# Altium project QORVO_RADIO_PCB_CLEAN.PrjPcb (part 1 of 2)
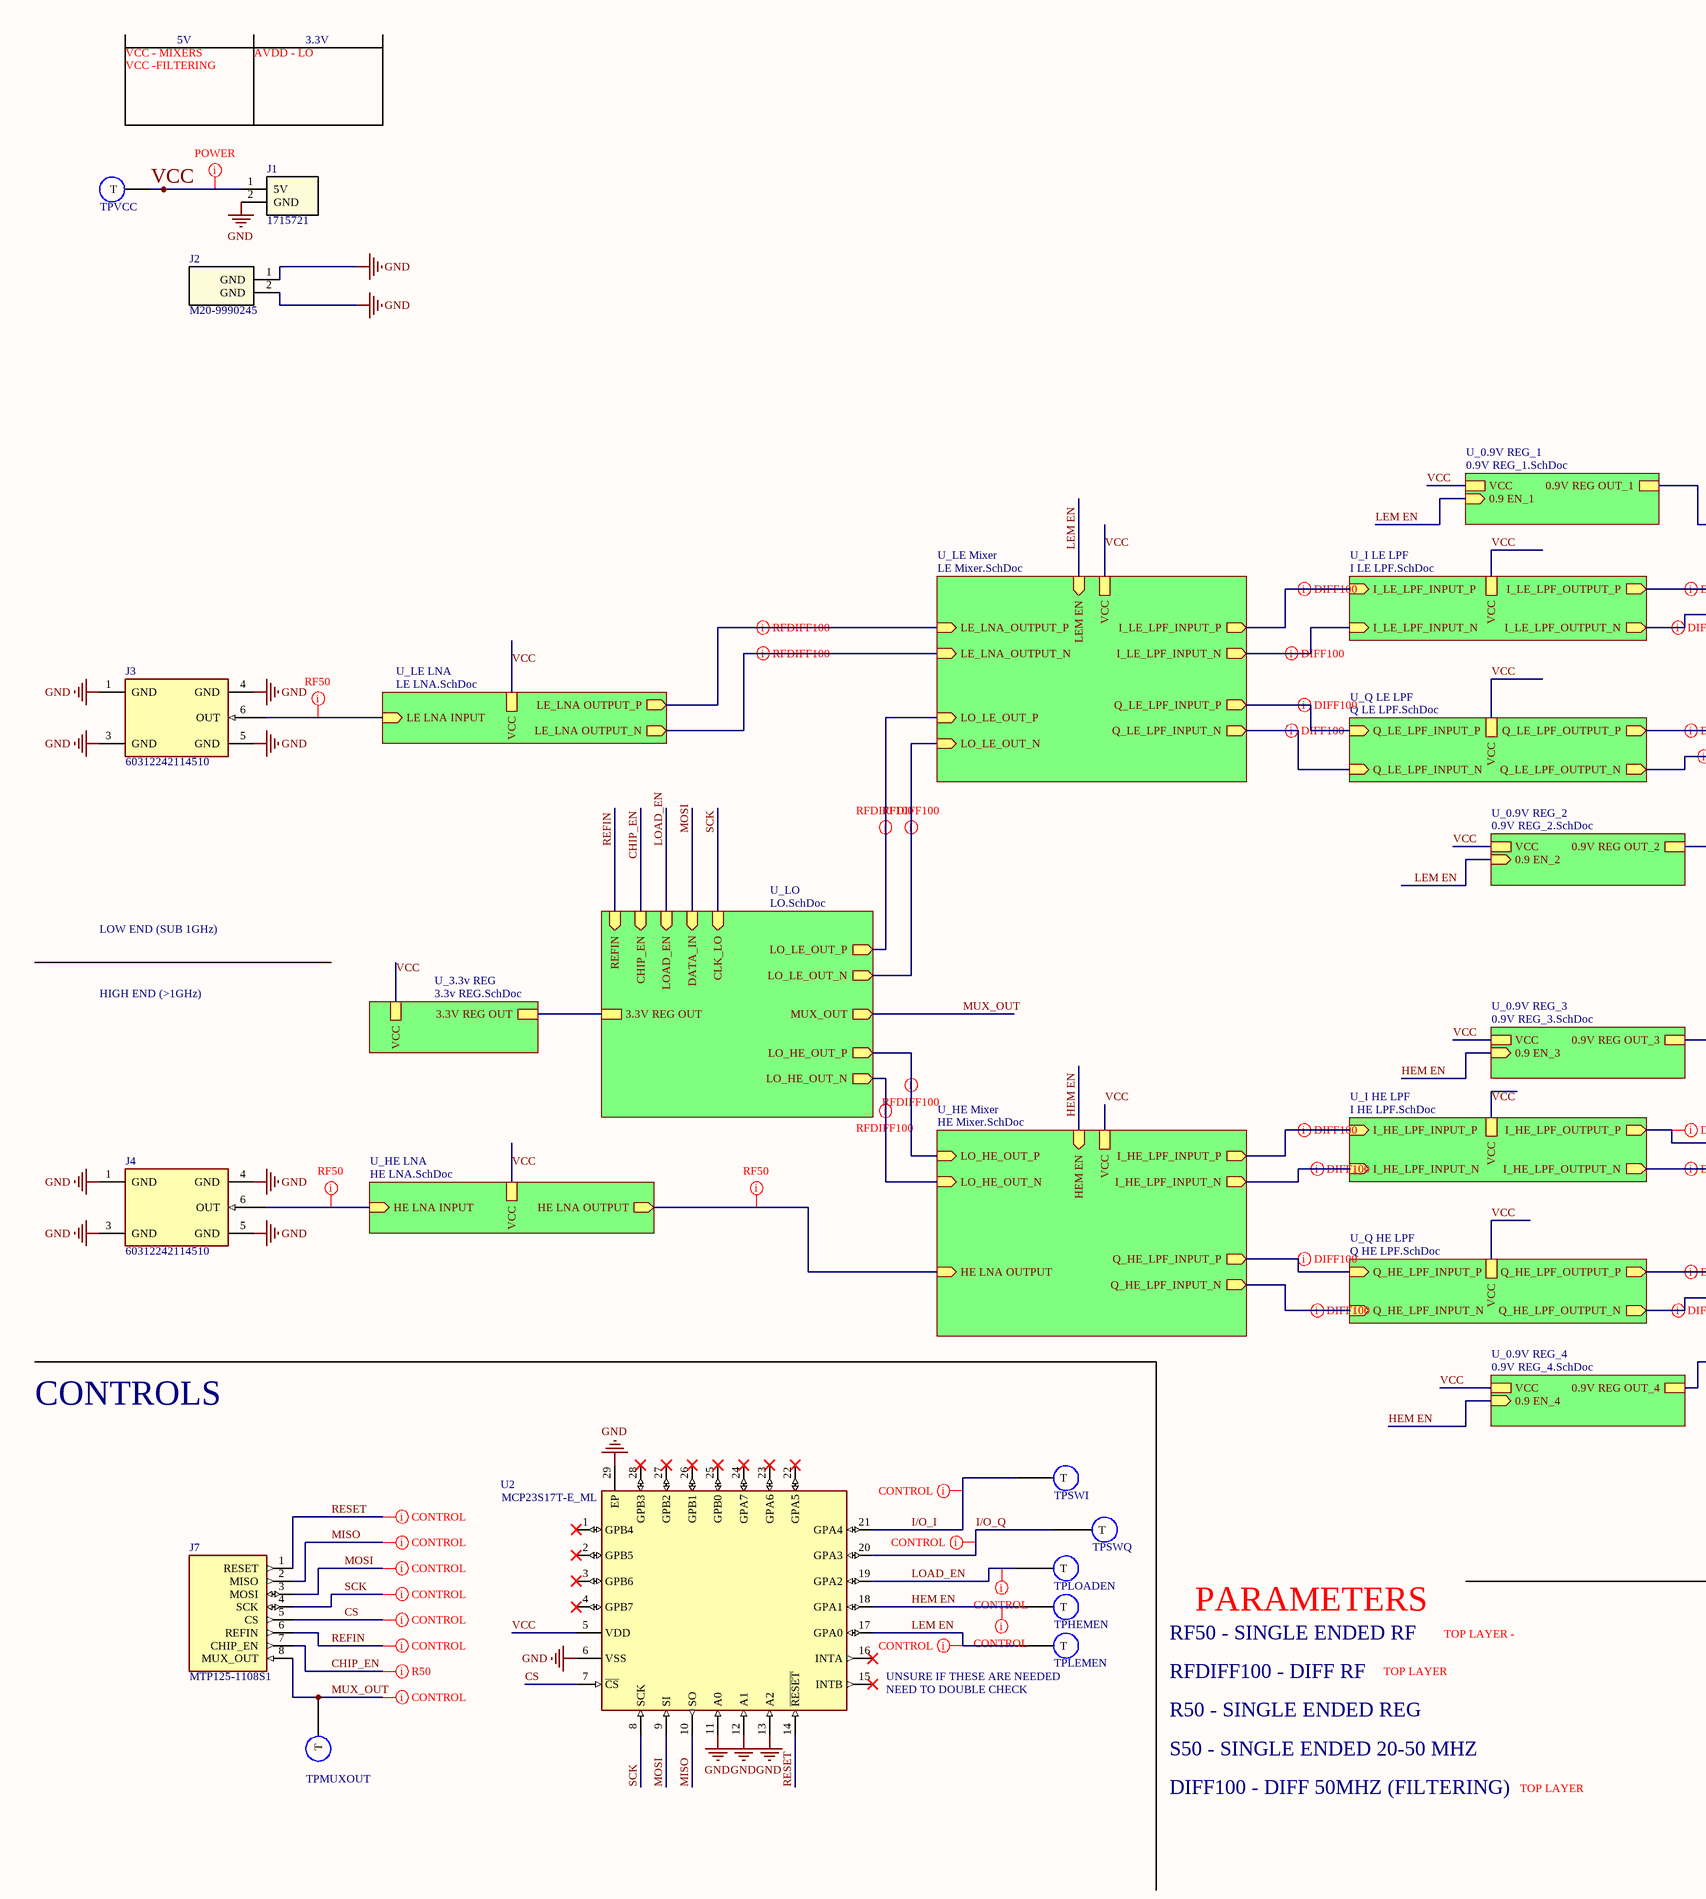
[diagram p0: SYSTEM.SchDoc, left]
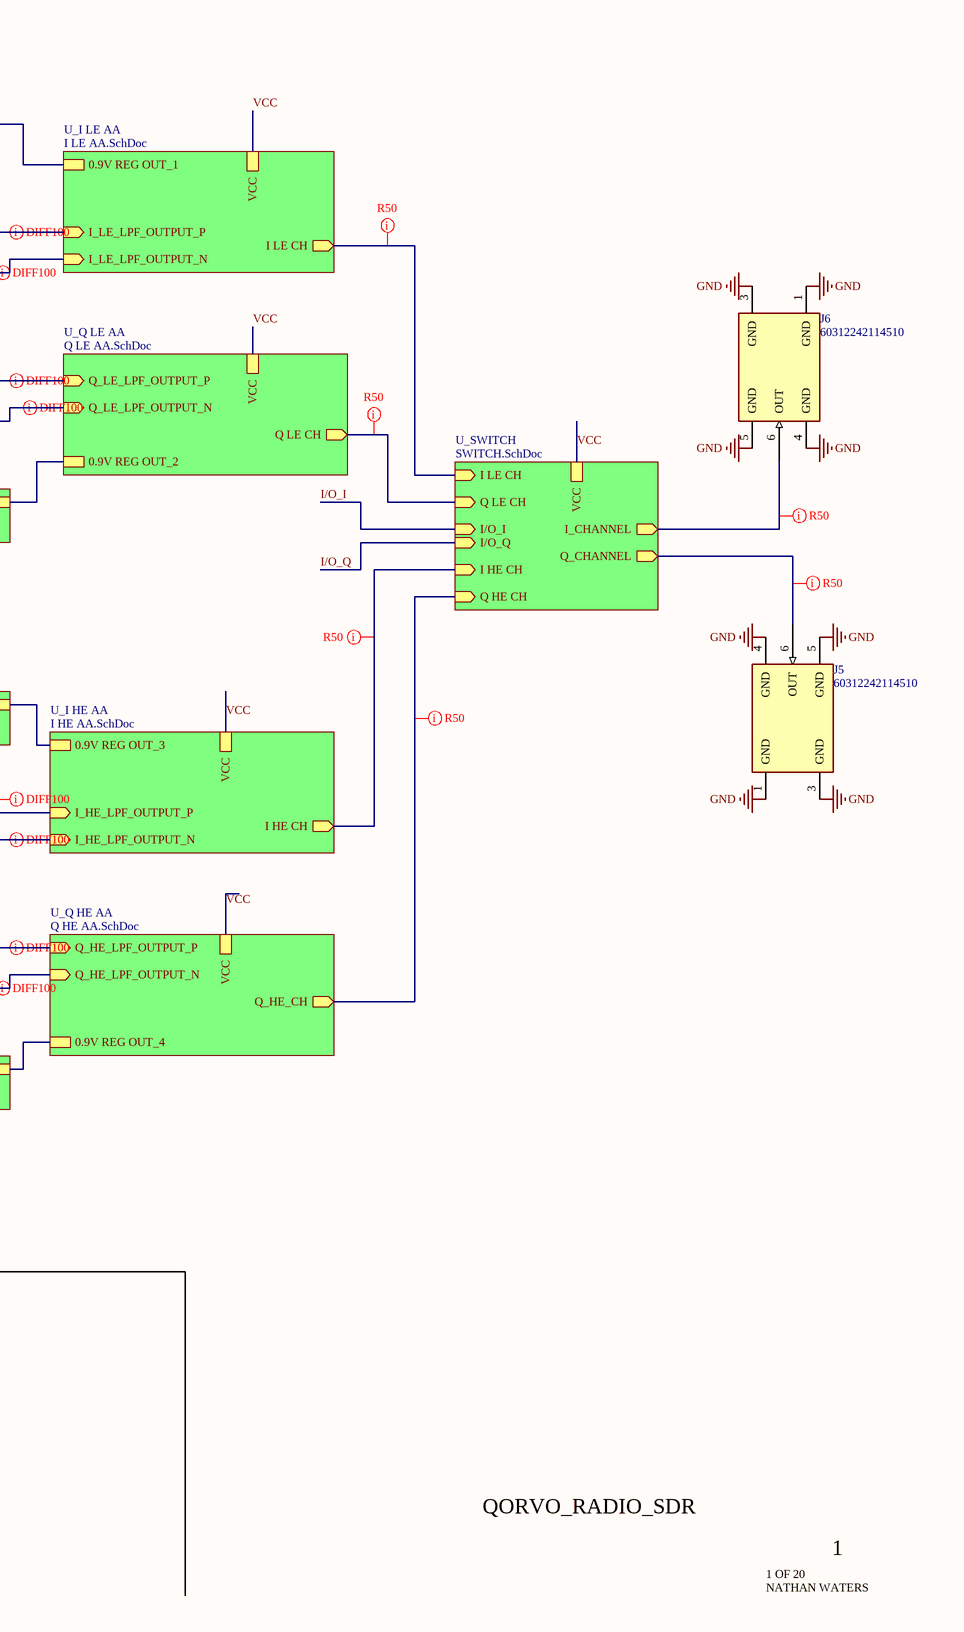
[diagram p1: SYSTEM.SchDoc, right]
20 sheets, 302 parts. Net scope: hierarchical (ports join the sheet entries above them; power ports are global).
Board file: QORVO_RADIO_PCB_FINAL.PcbDoc
Sheets:
  SYSTEM.SchDoc
    U_HE LNA = HE LNA.SchDoc
    U_3.3v REG = 3.3v REG.SchDoc
    U_SWITCH = SWITCH.SchDoc
    U_0.9V REG_1 = 0.9V REG_1.SchDoc
    U_0.9V REG_2 = 0.9V REG_2.SchDoc
    U_0.9V REG_3 = 0.9V REG_3.SchDoc
    U_0.9V REG_4 = 0.9V REG_4.SchDoc
    U_LE LNA = LE LNA.SchDoc
    U_LE Mixer = LE Mixer.SchDoc
    U_LO = LO.SchDoc
    U_HE Mixer = HE Mixer.SchDoc
    U_I LE LPF = I LE LPF.SchDoc
    U_Q LE LPF = Q LE LPF.SchDoc
    U_I HE LPF = I HE LPF.SchDoc
    U_Q HE LPF = Q HE LPF.SchDoc
    U_Q HE AA = Q HE AA.SchDoc
    U_I HE AA = I HE AA.SchDoc
    U_Q LE AA = Q LE AA.SchDoc
    U_I LE AA = I LE AA.SchDoc

## Sheet SYSTEM.SchDoc
size C; SheetNumber: 1; SheetTotal: 20

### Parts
J1  1715721  [1715721]
J2  M20-9990245  [GND_TEST]
J3  60312242114510  [60312242114510]
J4  60312242114510  [60312242114510]
J5  60312242114510  [60312242114510]
J6  60312242114510  [60312242114510]
J7  MTP125-1108S1  [M20-9990845]
TPHEMEN  TEST_POINT  [TEST POINT]  (value not drawn)  (no BOM)
TPLEMEN  TEST_POINT  [TEST POINT]  (value not drawn)  (no BOM)
TPLOADEN  TEST_POINT  [TEST POINT]  (value not drawn)  (no BOM)
TPMUXOUT  TEST_POINT  [TEST POINT]  (value not drawn)  (no BOM)
TPSWI  TEST_POINT  [TEST POINT]  (value not drawn)  (no BOM)
TPSWQ  TEST_POINT  [TEST POINT]  (value not drawn)  (no BOM)
TPVCC  TEST_POINT  [TEST POINT]  (value not drawn)  (no BOM)
U2  MCP23S17T-E_ML  [MCP23S17T-E_ML]

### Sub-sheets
U_0.9V REG_1 = 0.9V REG_1.SchDoc: VCC, 0.9V REG OUT_1, 0.9 EN_1 (in)
U_0.9V REG_2 = 0.9V REG_2.SchDoc: VCC, 0.9V REG OUT_2, 0.9 EN_2 (in)
U_0.9V REG_3 = 0.9V REG_3.SchDoc: VCC, 0.9V REG OUT_3, 0.9 EN_3 (in)
U_0.9V REG_4 = 0.9V REG_4.SchDoc: VCC, 0.9V REG OUT_4, 0.9 EN_4 (in)
U_3.3v REG = 3.3v REG.SchDoc: 3.3V REG OUT, VCC
U_HE LNA = HE LNA.SchDoc: HE LNA INPUT (in), HE LNA OUTPUT (out), VCC
U_HE Mixer = HE Mixer.SchDoc: HE LNA OUTPUT (in), HEM EN (in), VCC, LO_HE_OUT_N (in), LO_HE_OUT_P (in), Q_HE_LPF_INPUT_P (out), Q_HE_LPF_INPUT_N (out), I_HE_LPF_INPUT_N (out), I_HE_LPF_INPUT_P (out)
U_I HE AA = I HE AA.SchDoc: I_HE_LPF_OUTPUT_P (in), I_HE_LPF_OUTPUT_N (in), VCC, 0.9V REG OUT_3, I HE CH (out)
U_I HE LPF = I HE LPF.SchDoc: I_HE_LPF_INPUT_P (in), I_HE_LPF_INPUT_N (in), VCC, I_HE_LPF_OUTPUT_P (out), I_HE_LPF_OUTPUT_N (out)
U_I LE AA = I LE AA.SchDoc: I_LE_LPF_OUTPUT_P (in), I_LE_LPF_OUTPUT_N (in), VCC, 0.9V REG OUT_1, I LE CH (out)
U_I LE LPF = I LE LPF.SchDoc: I_LE_LPF_INPUT_P (in), I_LE_LPF_INPUT_N (in), VCC, I_LE_LPF_OUTPUT_P (out), I_LE_LPF_OUTPUT_N (out)
U_LE LNA = LE LNA.SchDoc: LE LNA INPUT (in), VCC, LE_LNA OUTPUT_P (out), LE_LNA OUTPUT_N (out)
U_LE Mixer = LE Mixer.SchDoc: LE_LNA_OUTPUT_P (in), LE_LNA_OUTPUT_N (in), LEM EN (in), VCC, LO_LE_OUT_N (in), Q_LE_LPF_INPUT_P (out), Q_LE_LPF_INPUT_N (out), I_LE_LPF_INPUT_N (out), I_LE_LPF_INPUT_P (out), LO_LE_OUT_P (in)
U_LO = LO.SchDoc: CLK_LO (in), DATA_IN (in), LOAD_EN (in), CHIP_EN (in), LO_LE_OUT_N (out), REFIN (in), MUX_OUT (out), LO_HE_OUT_P (out), LO_HE_OUT_N (out), 3.3V REG OUT, LO_LE_OUT_P (out)
U_Q HE AA = Q HE AA.SchDoc: Q_HE_LPF_OUTPUT_P (in), Q_HE_LPF_OUTPUT_N (in), VCC, 0.9V REG OUT_4, Q_HE_CH (out)
U_Q HE LPF = Q HE LPF.SchDoc: Q_HE_LPF_INPUT_P (in), Q_HE_LPF_INPUT_N (in), VCC, Q_HE_LPF_OUTPUT_P (out), Q_HE_LPF_OUTPUT_N (out)
U_Q LE AA = Q LE AA.SchDoc: Q_LE_LPF_OUTPUT_P (in), Q_LE_LPF_OUTPUT_N (in), VCC, 0.9V REG OUT_2, Q LE CH (out)
U_Q LE LPF = Q LE LPF.SchDoc: Q_LE_LPF_INPUT_P (in), Q_LE_LPF_INPUT_N (in), VCC, Q_LE_LPF_OUTPUT_P (out), Q_LE_LPF_OUTPUT_N (out)
U_SWITCH = SWITCH.SchDoc: I/O_I (in), I HE CH (in), Q HE CH (in), I/O_Q (in), VCC, I_CHANNEL (out), I LE CH (in), Q LE CH (in), Q_CHANNEL (out)

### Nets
GND: J1.2(GND) J2.1(GND) J2.2(GND) J3.1(GND) J3.3(GND) J3.4(GND) J3.5(GND) J4.1(GND) J4.3(GND) J4.4(GND) J4.5(GND) J5.1(GND) J5.3(GND) J5.4(GND) J5.5(GND) J6.1(GND) J6.3(GND) J6.4(GND) J6.5(GND) U2.6(VSS) U2.11(A0) U2.12(A1) U2.13(A2) U2.29(EP)
0.9V REG OUT_1: sheet U_0.9V REG_1/0.9V REG OUT_1, sheet U_I LE AA/0.9V REG OUT_1
0.9V REG OUT_2: sheet U_0.9V REG_2/0.9V REG OUT_2, sheet U_Q LE AA/0.9V REG OUT_2
0.9V REG OUT_3: sheet U_0.9V REG_3/0.9V REG OUT_3, sheet U_I HE AA/0.9V REG OUT_3
0.9V REG OUT_4: sheet U_0.9V REG_4/0.9V REG OUT_4, sheet U_Q HE AA/0.9V REG OUT_4
AVDD: sheet U_3.3v REG/3.3V REG OUT, sheet U_LO/3.3V REG OUT
CHIP_EN: J7.7(CHIP_EN) ; sheet U_LO/CHIP_EN
CS: J7.5(CS) U2.7(~{CS})
HE LNA OUTPUT: sheet U_HE LNA/HE LNA OUTPUT, sheet U_HE Mixer/HE LNA OUTPUT
HEM EN: TPHEMEN.1(T) U2.18(GPA1) ; sheet U_0.9V REG_3/0.9 EN_3, sheet U_0.9V REG_4/0.9 EN_4, sheet U_HE Mixer/HEM EN
I HE CH: sheet U_SWITCH/I HE CH, sheet U_I HE AA/I HE CH
I LE CH: sheet U_SWITCH/I LE CH, sheet U_I LE AA/I LE CH
I/O_I: TPSWI.1(T) U2.21(GPA4) ; sheet U_SWITCH/I/O_I
I/O_Q: TPSWQ.1(T) U2.20(GPA3) ; sheet U_SWITCH/I/O_Q
I_HE_LPF_INPUT_N: sheet U_HE Mixer/I_HE_LPF_INPUT_N, sheet U_I HE LPF/I_HE_LPF_INPUT_N
I_HE_LPF_INPUT_P: sheet U_HE Mixer/I_HE_LPF_INPUT_P, sheet U_I HE LPF/I_HE_LPF_INPUT_P
I_HE_LPF_OUTPUT_N: sheet U_I HE LPF/I_HE_LPF_OUTPUT_N, sheet U_I HE AA/I_HE_LPF_OUTPUT_N
I_HE_LPF_OUTPUT_P: sheet U_I HE LPF/I_HE_LPF_OUTPUT_P, sheet U_I HE AA/I_HE_LPF_OUTPUT_P
I_LE_LPF_INPUT_N: sheet U_LE Mixer/I_LE_LPF_INPUT_N, sheet U_I LE LPF/I_LE_LPF_INPUT_N
I_LE_LPF_INPUT_P: sheet U_LE Mixer/I_LE_LPF_INPUT_P, sheet U_I LE LPF/I_LE_LPF_INPUT_P
I_LE_LPF_OUTPUT_N: sheet U_I LE LPF/I_LE_LPF_OUTPUT_N, sheet U_I LE AA/I_LE_LPF_OUTPUT_N
I_LE_LPF_OUTPUT_P: sheet U_I LE LPF/I_LE_LPF_OUTPUT_P, sheet U_I LE AA/I_LE_LPF_OUTPUT_P
LE_LNA OUTPUT_N: sheet U_LE LNA/LE_LNA OUTPUT_N, sheet U_LE Mixer/LE_LNA_OUTPUT_N
LE_LNA OUTPUT_P: sheet U_LE LNA/LE_LNA OUTPUT_P, sheet U_LE Mixer/LE_LNA_OUTPUT_P
LEM EN: TPLEMEN.1(T) U2.17(GPA0) ; sheet U_0.9V REG_1/0.9 EN_1, sheet U_0.9V REG_2/0.9 EN_2, sheet U_LE Mixer/LEM EN
LO_HE_OUT_N: sheet U_LO/LO_HE_OUT_N, sheet U_HE Mixer/LO_HE_OUT_N
LO_HE_OUT_P: sheet U_LO/LO_HE_OUT_P, sheet U_HE Mixer/LO_HE_OUT_P
LO_LE_OUT_N: sheet U_LE Mixer/LO_LE_OUT_N, sheet U_LO/LO_LE_OUT_N
LO_LE_OUT_P: sheet U_LE Mixer/LO_LE_OUT_P, sheet U_LO/LO_LE_OUT_P
LOAD_EN: TPLOADEN.1(T) U2.19(GPA2) ; sheet U_LO/LOAD_EN
MISO: J7.2(MISO) U2.10(SO)
MOSI: J7.3(MOSI) U2.9(SI) ; sheet U_LO/DATA_IN
MUX_OUT: J7.8(MUX_OUT) TPMUXOUT.1(T) ; sheet U_LO/MUX_OUT
Q HE CH: sheet U_SWITCH/Q HE CH, sheet U_Q HE AA/Q_HE_CH
Q LE CH: sheet U_SWITCH/Q LE CH, sheet U_Q LE AA/Q LE CH
Q_HE_LPF_INPUT_N: sheet U_HE Mixer/Q_HE_LPF_INPUT_N, sheet U_Q HE LPF/Q_HE_LPF_INPUT_N
Q_HE_LPF_INPUT_P: sheet U_HE Mixer/Q_HE_LPF_INPUT_P, sheet U_Q HE LPF/Q_HE_LPF_INPUT_P
Q_HE_LPF_OUTPUT_N: sheet U_Q HE LPF/Q_HE_LPF_OUTPUT_N, sheet U_Q HE AA/Q_HE_LPF_OUTPUT_N
Q_HE_LPF_OUTPUT_P: sheet U_Q HE LPF/Q_HE_LPF_OUTPUT_P, sheet U_Q HE AA/Q_HE_LPF_OUTPUT_P
Q_LE_LPF_INPUT_N: sheet U_LE Mixer/Q_LE_LPF_INPUT_N, sheet U_Q LE LPF/Q_LE_LPF_INPUT_N
Q_LE_LPF_INPUT_P: sheet U_LE Mixer/Q_LE_LPF_INPUT_P, sheet U_Q LE LPF/Q_LE_LPF_INPUT_P
Q_LE_LPF_OUTPUT_N: sheet U_Q LE LPF/Q_LE_LPF_OUTPUT_N, sheet U_Q LE AA/Q_LE_LPF_OUTPUT_N
Q_LE_LPF_OUTPUT_P: sheet U_Q LE LPF/Q_LE_LPF_OUTPUT_P, sheet U_Q LE AA/Q_LE_LPF_OUTPUT_P
REFIN: J7.6(REFIN) ; sheet U_LO/REFIN
RESET: J7.1(RESET) U2.14(~{RESET})
SCK: J7.4(SCK) U2.8(SCK) ; sheet U_LO/CLK_LO
VCC: J1.1(5V) TPVCC.1(T) U2.5(VDD) ; sheet U_HE LNA/VCC, sheet U_3.3v REG/VCC, sheet U_SWITCH/VCC, sheet U_0.9V REG_1/VCC, sheet U_0.9V REG_2/VCC, sheet U_0.9V REG_3/VCC, sheet U_0.9V REG_4/VCC, sheet U_LE LNA/VCC, sheet U_LE Mixer/VCC, sheet U_HE Mixer/VCC, sheet U_I LE LPF/VCC, sheet U_Q LE LPF/VCC, sheet U_I HE LPF/VCC, sheet U_Q HE LPF/VCC, sheet U_Q HE AA/VCC, sheet U_I HE AA/VCC, sheet U_Q LE AA/VCC, sheet U_I LE AA/VCC
NetC53_1: J3.6(OUT) ; sheet U_LE LNA/LE LNA INPUT
NetC71_1: J4.6(OUT) ; sheet U_HE LNA/HE LNA INPUT
NetJ5_6: J5.6(OUT) ; sheet U_SWITCH/Q_CHANNEL
NetJ6_6: J6.6(OUT) ; sheet U_SWITCH/I_CHANNEL

Not connected (* = marked no-connect by the designer): U2 1(GPB4)* 2(GPB5)* 3(GPB6)* 4(GPB7)* 15(INTB)* 16(INTA)* 22(GPA5)* 23(GPA6)* 24(GPA7)* 25(GPB0)* 26(GPB1)* 27(GPB2)* 28(GPB3)*

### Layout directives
net class RF50: HE LNA OUTPUT, NetC53_1, NetC71_1
differential pair; differential pair class RFDIFF100: LE_LNA OUTPUT_N, LE_LNA OUTPUT_P, LO_HE_OUT_N, LO_HE_OUT_P, LO_LE_OUT_N, LO_LE_OUT_P
differential pair; differential pair class DIFF100: I_HE_LPF_INPUT_N, I_HE_LPF_INPUT_P, I_HE_LPF_OUTPUT_N, I_HE_LPF_OUTPUT_P, I_LE_LPF_INPUT_N, I_LE_LPF_INPUT_P, I_LE_LPF_OUTPUT_N, I_LE_LPF_OUTPUT_P, Q_HE_LPF_INPUT_N, Q_HE_LPF_INPUT_P, Q_HE_LPF_OUTPUT_N, Q_HE_LPF_OUTPUT_P, Q_LE_LPF_INPUT_N, Q_LE_LPF_INPUT_P, Q_LE_LPF_OUTPUT_N, Q_LE_LPF_OUTPUT_P
net class R50: CHIP_EN, I HE CH, I LE CH, NetJ5_6, NetJ6_6, Q HE CH, Q LE CH
net class CONTROLS: CS, HEM EN, I/O_I, I/O_Q, LEM EN, LOAD_EN, MISO, MOSI, MUX_OUT, REFIN, RESET, SCK
net class POWER: VCC

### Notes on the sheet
- VCC - MIXERS
- VCC -FILTERING
- 5V
- AVDD - LO
- 3.3V
- LOW END (SUB 1GHz)
- HIGH END (>1GHz)
- CONTROLS
- PARAMETERS
- UNSURE IF THESE ARE NEEDED
- (near U2) NEED TO DOUBLE CHECK
- RF50 - SINGLE ENDED RF
- RFDIFF100 - DIFF RF
- TOP LAYER
- TOP LAYER -
- R50 - SINGLE ENDED REG
- S50 - SINGLE ENDED 20-50 MHZ
- DIFF100 - DIFF 50MHZ (FILTERING)
- QORVO_RADIO_SDR
- NATHAN WATERS
- 1 OF 20
- 1

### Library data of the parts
J1 = 1715721: 1x2P 17.5A 250V Green 14~30 Direct Insert 5.08mm 1 2 Plugin,P=5.08mm Screw Terminal Blocks ROHS; Mfr_Name: Phoenix Contact
J2 = GND_TEST: 3A Direct Insert Policy 2.54mm 2P 6.1mm -40℃~+105℃ 3mm 2.54mm Single Row Brass Black Plugin,P=2.54mm  Pin Headers ROHS; Mfr_Name: Harwin
J3-J6 = 60312242114510: 1 SMA Board Edge 18GHz 50Ω -  RF Connectors / Coaxial Connectors ROHS
J7 = MTP125-1108S1: Direct Insert Policy 2.5mm 8P 6mm -40℃~+105℃ 3mm 2.54mm Single Row Black Brass 1x8P Plugin,P=2.54mm Pin Headers ROHS; MP: M20-9990645
TPHEMEN TPLEMEN TPLOADEN TPMUXOUT TPSWI TPSWQ TPVCC = TEST_POINT: TEST POINT
U2 = MCP23S17T-E_ML: 10MHz SPI QFN-28-EP(6x6) I/O Expanders ROHS; Manufacturer_Name: Microchip; Manufacturer_Part_Number: MCP23S17T-E/ML

## Sheet HE LNA.SchDoc
size A; SheetNumber: 8; SheetTotal: 20
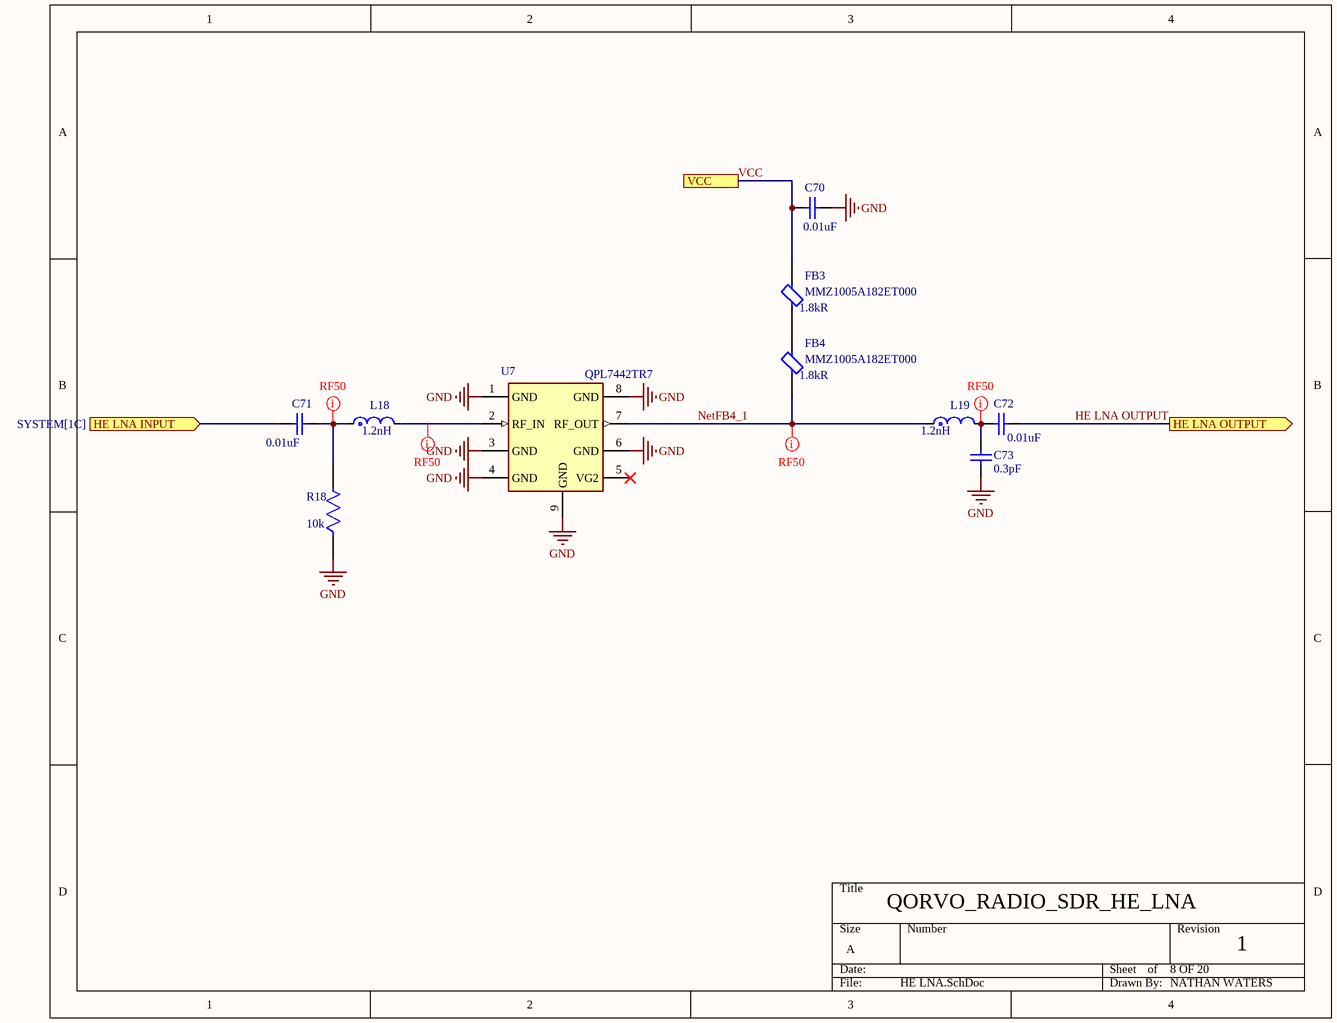
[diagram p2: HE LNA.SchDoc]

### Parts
C70  CAPACITANCE: 0.01uF  [0402 CAP_IND_RES]  (hidden comment: GRM155R71C103KA01D)
C71  CAPACITANCE: 0.01uF  [0402 CAP_IND_RES]  (hidden comment: GRM155R71C103KA01D)
C72  CAPACITANCE: 0.01uF  [0402 CAP_IND_RES]  (hidden comment: GRM155R71C103KA01D)
C73  CAPACITANCE: 0.3pF  [0402 CAP_IND_RES]  (hidden comment: GJM1555C1HR30WB01D)
FB3  MMZ1005A182ET000  Impeadance: 1.8kR  [0402 CAP_IND_RES]
FB4  MMZ1005A182ET000  Impeadance: 1.8kR  [0402 CAP_IND_RES]
L18  Inductance: 1.2nH  [0402 CAP_IND_RES]  (hidden comment: LQG15HS1N2S02D)
L19  Inductance: 1.2nH  [0402 CAP_IND_RES]  (hidden comment: LQG15HS1N2S02D)
R18  Resistance: 10k  [0402 CAP_IND_RES]  (hidden comment: CRCW040210K0FKEDC)
U7  QPL7442TR7  [QPL7442TR7]

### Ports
HE LNA INPUT (in, see SYSTEM[1C]), HE LNA OUTPUT (out, see SYSTEM[2C], HE Mixer[1C]), VCC (see SYSTEM[2C], 0.9V REG_1[3B], 0.9V REG_2[3B], 0.9V REG_3[3B], 0.9V REG_4[3B], 3.3v REG[3B], HE Mixer[3C], I HE AA[1B], I HE LPF[1A], I LE AA[1B], I LE LPF[1A], LE LNA[2A], LE Mixer[3C], Q HE AA[1B], Q HE LPF[1A], Q LE AA[1B], Q LE LPF[1B], SWITCH[4B])

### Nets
GND: C70.2 C73.1 R18.1 U7.1(GND) U7.3(GND) U7.4(GND) U7.6(GND) U7.8(GND) U7.9(GND)
HE LNA OUTPUT: C72.2 ; port HE LNA OUTPUT
NetFB4_1: FB4.1 L19.1 U7.7(RF_OUT)
VCC: C70.1 FB3.2 ; port VCC
NetC71_1: C71.1 ; port HE LNA INPUT
NetC71_2: C71.2 L18.1 R18.2
NetC72_1: C72.1 C73.2 L19.2
NetFB3_1: FB3.1 FB4.2
NetL18_2: L18.2 U7.2(RF_IN)

Not connected (* = marked no-connect by the designer): U7 5(VG2)*

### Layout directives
net class RF50: NetC71_2, NetC72_1, NetFB4_1, NetL18_2

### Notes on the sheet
- QORVO_RADIO_SDR_HE_LNA
- 8 OF 20
- 1
- NATHAN WATERS

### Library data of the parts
C70-C72 = 0402_CAP: Chip Capacitor, 10 nF, 16 V, 10%, -55 to 125 degC, 0402 (1005 Metric), RoHS, Tape and Reel
C73 = 0402_CAP: Multi-Layer Ceramic Capacitor 0.3pF C0G  ±0.05pF 0402 Paper T/R
FB3 FB4 = 0402_FERRITE_BEADS: Signal Line Ferrite Bead 1800Ω @ 100MHz 200mA DCR 2100mΩ SMD 0402
L18 L19 = 0402_IND: 1A 1.2nH 70mΩ 0402 Inductors (SMD) ROHS
R18 = 0402_RES: RES 10K OHM 1% 1/16W 0402
U7 = QPL7442TR7: Qorvo QPL7442TR7

## Sheet 3.3v REG.SchDoc
size A; SheetNumber: 3; SheetTotal: 20
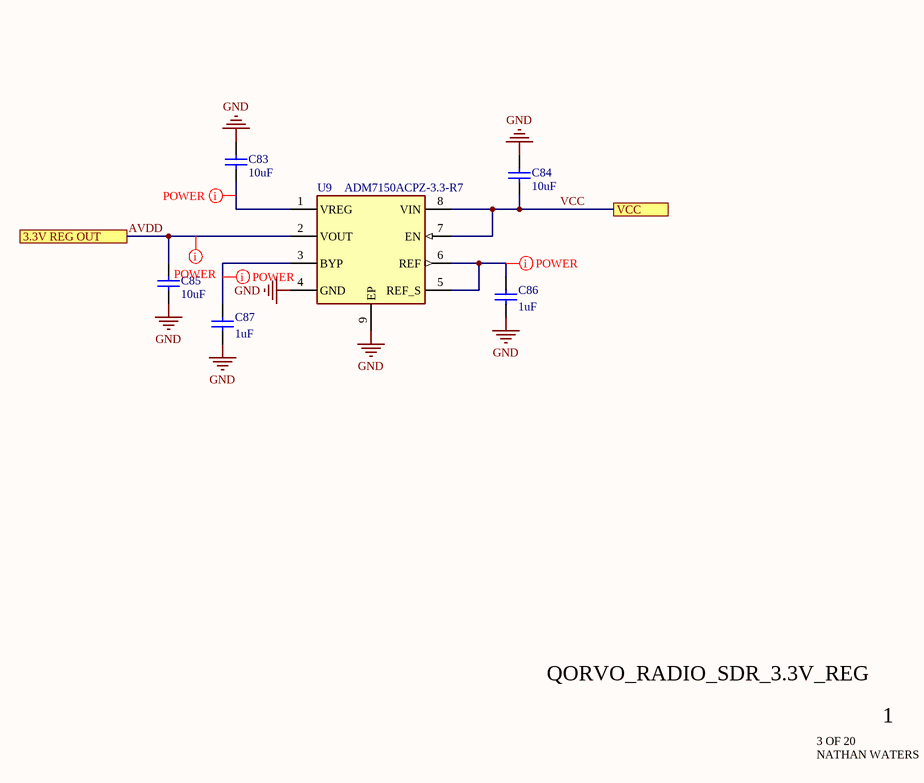
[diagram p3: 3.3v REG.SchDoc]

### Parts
C83  CAPACITANCE: 10uF  [0603_CAP]  (hidden comment: GRM188C81C106MA73D)
C84  CAPACITANCE: 10uF  [0603_CAP]  (hidden comment: GRM188C81C106MA73D)
C85  CAPACITANCE: 10uF  [0603_CAP]  (hidden comment: GRM188C81C106MA73D)
C86  CAPACITANCE: 1uF  [0402 CAP_IND_RES]  (hidden comment: GRM155R61H105KE05D)
C87  CAPACITANCE: 1uF  [0402 CAP_IND_RES]  (hidden comment: GRM155R61H105KE05D)
U9  ADM7150ACPZ-3.3-R7  [ADM7150ACPZ-3.3-R7]

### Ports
3.3V REG OUT (see SYSTEM[2C], LO[1A]), VCC (see SYSTEM[1C], 0.9V REG_1[3B], 0.9V REG_2[3B], 0.9V REG_3[3B], 0.9V REG_4[3B], HE LNA[2A], HE Mixer[3C], I HE AA[1B], I HE LPF[1A], I LE AA[1B], I LE LPF[1A], LE LNA[2A], LE Mixer[3C], Q HE AA[1B], Q HE LPF[1A], Q LE AA[1B], Q LE LPF[1B], SWITCH[4B])

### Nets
GND: C83.2 C84.2 C85.1 C86.1 C87.1 U9.4(GND) U9.9(EP)
AVDD: C85.2 U9.2(VOUT) ; port 3.3V REG OUT
VCC: C84.1 U9.7(EN) U9.8(VIN) ; port VCC
NetC83_1: C83.1 U9.1(VREG)
NetC86_2: C86.2 U9.5(REF_S) U9.6(REF)
NetC87_2: C87.2 U9.3(BYP)

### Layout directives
net class POWER: AVDD, NetC83_1, NetC86_2, NetC87_2

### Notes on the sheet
- QORVO_RADIO_SDR_3.3V_REG
- 3 OF 20
- 1
- NATHAN WATERS

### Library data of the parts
C83-C85 = 0603_CAP: Chip Multilayer Ceramic Capacitors for General Purpose, 0603, 10uF, X6S, 22%, 20%, 16V
C86 C87 = 0402_CAP: 50V 1uF X5R ±10% 0402  Multilayer Ceramic Capacitors MLCC - SMD/SMT ROHS
U9 = ADM7150ACPZ-3.3-R7: 800mA 68dB@(1MHz) Fixed 3.3V Positive electrode 16V LFCSP-8-EP(3x3) Voltage Regulators - Linear, Low Drop Out (LDO) Regulators ROHS; Manufacturer_Name: Analog Devices

## Sheet SWITCH.SchDoc
size A; SheetNumber: 2; SheetTotal: 20
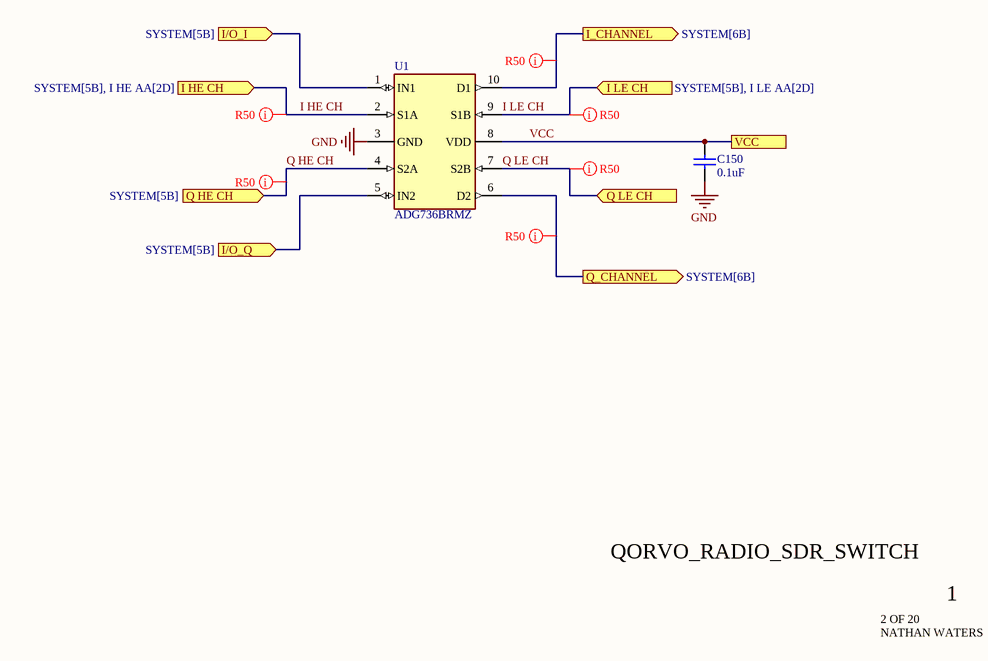
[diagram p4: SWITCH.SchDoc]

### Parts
C150  CAPACITANCE: 0.1uF  [0402 CAP_IND_RES]  (hidden comment: CL05B104KO5NNNC)
U1  ADG736BRMZ  [ADG736BRMZ]

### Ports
I HE CH (in, see SYSTEM[5B], I HE AA[2D]), I LE CH (in, see SYSTEM[5B], I LE AA[2D]), I/O_I (in, see SYSTEM[5B]), I/O_Q (in, see SYSTEM[5B]), I_CHANNEL (out, see SYSTEM[6B]), Q HE CH (in, see SYSTEM[5B]), Q LE CH (in, see SYSTEM[5B], Q LE AA[2D]), Q_CHANNEL (out, see SYSTEM[6B]), VCC (see SYSTEM[6B], 0.9V REG_1[3B], 0.9V REG_2[3B], 0.9V REG_3[3B], 0.9V REG_4[3B], 3.3v REG[3B], HE LNA[2A], HE Mixer[3C], I HE AA[1B], I HE LPF[1A], I LE AA[1B], I LE LPF[1A], LE LNA[2A], LE Mixer[3C], Q HE AA[1B], Q HE LPF[1A], Q LE AA[1B], Q LE LPF[1B])

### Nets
GND: C150.1 U1.3(GND)
I HE CH: U1.2(S1A) ; port I HE CH
I LE CH: U1.9(S1B) ; port I LE CH
I/O_I: U1.1(IN1) ; port I/O_I
I/O_Q: U1.5(IN2) ; port I/O_Q
Q HE CH: U1.4(S2A) ; port Q HE CH
Q LE CH: U1.7(S2B) ; port Q LE CH
VCC: C150.2 U1.8(VDD) ; port VCC
NetJ5_6: U1.6(D2) ; port Q_CHANNEL
NetJ6_6: U1.10(D1) ; port I_CHANNEL

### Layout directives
net class R50: I HE CH, I LE CH, NetJ5_6, NetJ6_6, Q HE CH, Q LE CH

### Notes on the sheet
- QORVO_RADIO_SDR_SWITCH
- 2 OF 20
- 1
- NATHAN WATERS

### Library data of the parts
C150 = 0402_CAP: 16V 100nF X7R ±10% 0402 Multilayer Ceramic Capacitors MLCC - SMD/SMT ROHS
U1 = ADG736BRMZ: 2 4Ω SPDT(SPDT) MSOP-10  Analog Switches, Multiplexers ROHS; Manufacturer_Name: Analog Devices

## Sheet 0.9V REG_1.SchDoc
size A; SheetNumber: 17; SheetTotal: 20
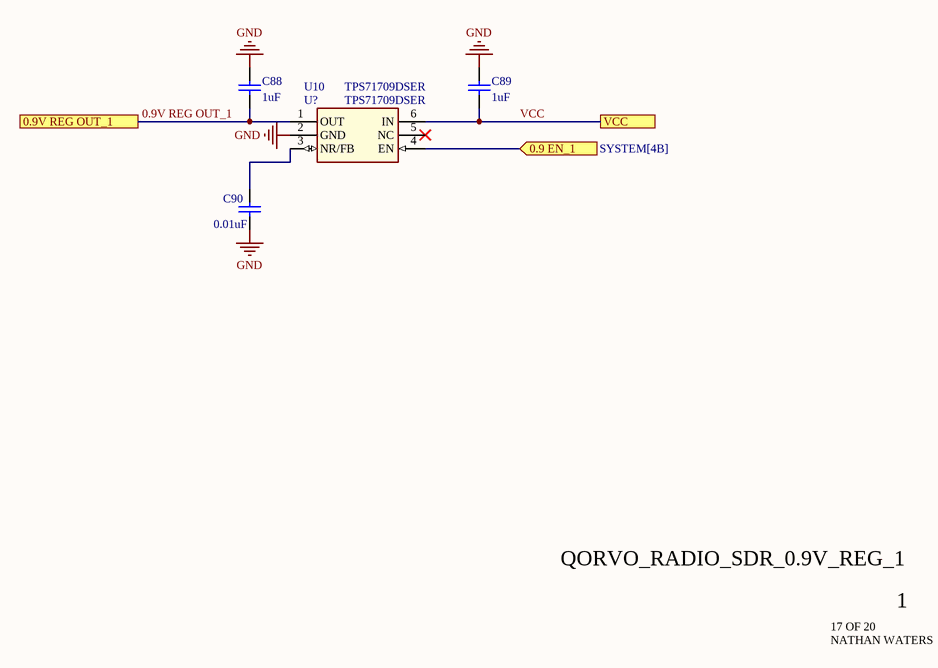
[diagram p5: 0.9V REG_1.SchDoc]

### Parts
C88  CAPACITANCE: 1uF  [0402 CAP_IND_RES]  (hidden comment: GRM155R61H105KE05D)
C89  CAPACITANCE: 1uF  [0402 CAP_IND_RES]  (hidden comment: GRM155R61H105KE05D)
C90  CAPACITANCE: 0.01uF  [0402 CAP_IND_RES]  (hidden comment: GRM155R71C103KA01D)
U10  TPS71709DSER  [TPS71709DSER]

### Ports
0.9 EN_1 (in, see SYSTEM[4B]), 0.9V REG OUT_1 (see SYSTEM[4B], I LE AA[4C]), VCC (see SYSTEM[4B], 0.9V REG_2[3B], 0.9V REG_3[3B], 0.9V REG_4[3B], 3.3v REG[3B], HE LNA[2A], HE Mixer[3C], I HE AA[1B], I HE LPF[1A], I LE AA[1B], I LE LPF[1A], LE LNA[2A], LE Mixer[3C], Q HE AA[1B], Q HE LPF[1A], Q LE AA[1B], Q LE LPF[1B], SWITCH[3B])

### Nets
GND: C88.2 C89.2 C90.1 U10.2(GND)
0.9V REG OUT_1: C88.1 U10.1(OUT) ; port 0.9V REG OUT_1
LEM EN: U10.4(EN) ; port 0.9 EN_1
VCC: C89.1 U10.6(IN) ; port VCC
NetC90_2: C90.2 U10.3(NR/FB)

Not connected (* = marked no-connect by the designer): U10 5(NC)*

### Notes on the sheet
- QORVO_RADIO_SDR_0.9V_REG_1
- 17 OF 20
- 1
- NATHAN WATERS

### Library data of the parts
C88 C89 = 0402_CAP: as C86 on sheet 3.3v REG
C90 = 0402_CAP: as C70 on sheet HE LNA
U10 = TPS71709DSER: 70dB@(100Hz) 150mA Fixed 900mV Positive electrode 6.5V WSON-6(1.5x1.5)  Voltage Regulators - Linear, Low Drop Out (LDO) Regulators ROHS; Mfr_Name: Texas Instruments

## Sheet 0.9V REG_2.SchDoc
size A; SheetNumber: 18; SheetTotal: 20
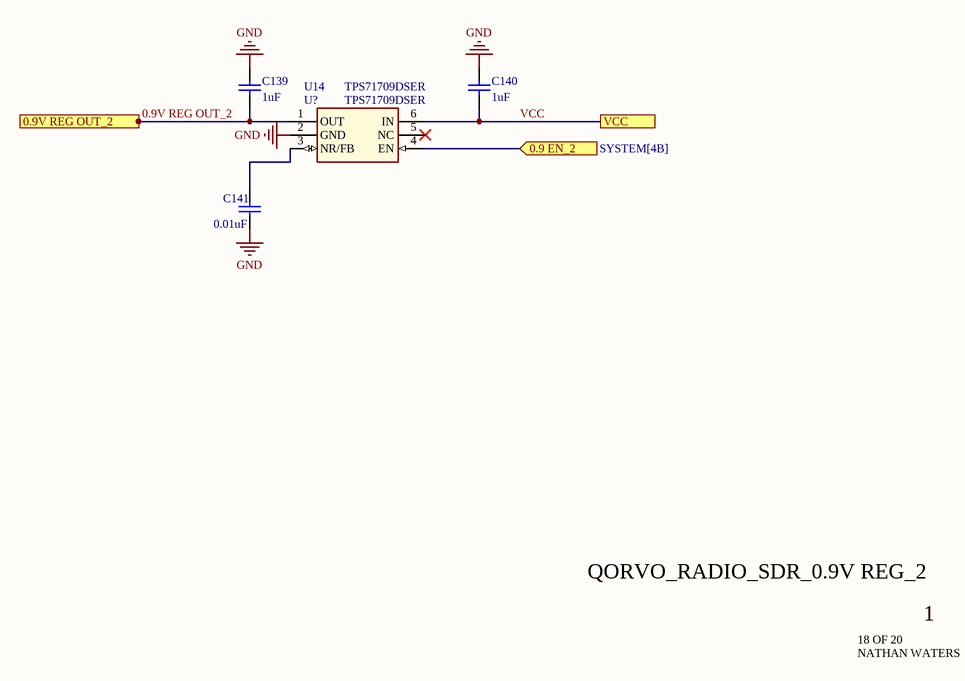
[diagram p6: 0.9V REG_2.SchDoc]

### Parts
C139  CAPACITANCE: 1uF  [0402 CAP_IND_RES]  (hidden comment: GRM155R61H105KE05D)
C140  CAPACITANCE: 1uF  [0402 CAP_IND_RES]  (hidden comment: GRM155R61H105KE05D)
C141  CAPACITANCE: 0.01uF  [0402 CAP_IND_RES]  (hidden comment: GRM155R71C103KA01D)
U14  TPS71709DSER  [TPS71709DSER]

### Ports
0.9 EN_2 (in, see SYSTEM[4B]), 0.9V REG OUT_2 (see SYSTEM[4B], Q LE AA[4C]), VCC (see SYSTEM[4B], 0.9V REG_1[3B], 0.9V REG_3[3B], 0.9V REG_4[3B], 3.3v REG[3B], HE LNA[2A], HE Mixer[3C], I HE AA[1B], I HE LPF[1A], I LE AA[1B], I LE LPF[1A], LE LNA[2A], LE Mixer[3C], Q HE AA[1B], Q HE LPF[1A], Q LE AA[1B], Q LE LPF[1B], SWITCH[3B])

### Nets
GND: C139.2 C140.2 C141.1 U14.2(GND)
0.9V REG OUT_2: C139.1 U14.1(OUT) ; port 0.9V REG OUT_2
LEM EN: U14.4(EN) ; port 0.9 EN_2
VCC: C140.1 U14.6(IN) ; port VCC
NetC141_2: C141.2 U14.3(NR/FB)

Not connected (* = marked no-connect by the designer): U14 5(NC)*

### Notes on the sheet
- QORVO_RADIO_SDR_0.9V REG_2
- 18 OF 20
- 1
- NATHAN WATERS

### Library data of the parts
C139 C140 = 0402_CAP: as C86 on sheet 3.3v REG
C141 = 0402_CAP: as C70 on sheet HE LNA
U14 = TPS71709DSER: as U10 on sheet 0.9V REG_1

## Sheet 0.9V REG_3.SchDoc
size A; SheetNumber: 19; SheetTotal: 20
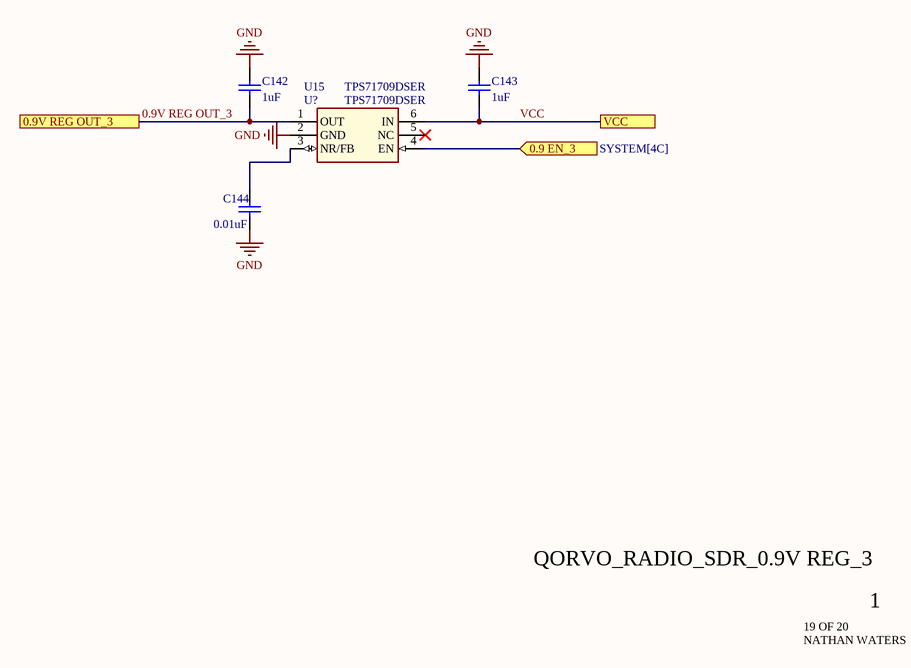
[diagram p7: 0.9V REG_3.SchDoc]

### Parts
C142  CAPACITANCE: 1uF  [0402 CAP_IND_RES]  (hidden comment: GRM155R61H105KE05D)
C143  CAPACITANCE: 1uF  [0402 CAP_IND_RES]  (hidden comment: GRM155R61H105KE05D)
C144  CAPACITANCE: 0.01uF  [0402 CAP_IND_RES]  (hidden comment: GRM155R71C103KA01D)
U15  TPS71709DSER  [TPS71709DSER]

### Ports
0.9 EN_3 (in, see SYSTEM[4C]), 0.9V REG OUT_3 (see SYSTEM[4C], I HE AA[4C]), VCC (see SYSTEM[4C], 0.9V REG_1[3B], 0.9V REG_2[3B], 0.9V REG_4[3B], 3.3v REG[3B], HE LNA[2A], HE Mixer[3C], I HE AA[1B], I HE LPF[1A], I LE AA[1B], I LE LPF[1A], LE LNA[2A], LE Mixer[3C], Q HE AA[1B], Q HE LPF[1A], Q LE AA[1B], Q LE LPF[1B], SWITCH[3B])

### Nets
GND: C142.2 C143.2 C144.1 U15.2(GND)
0.9V REG OUT_3: C142.1 U15.1(OUT) ; port 0.9V REG OUT_3
HEM EN: U15.4(EN) ; port 0.9 EN_3
VCC: C143.1 U15.6(IN) ; port VCC
NetC144_2: C144.2 U15.3(NR/FB)

Not connected (* = marked no-connect by the designer): U15 5(NC)*

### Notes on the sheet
- QORVO_RADIO_SDR_0.9V REG_3
- 19 OF 20
- 1
- NATHAN WATERS

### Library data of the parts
C142 C143 = 0402_CAP: as C86 on sheet 3.3v REG
C144 = 0402_CAP: as C70 on sheet HE LNA
U15 = TPS71709DSER: as U10 on sheet 0.9V REG_1

## Sheet 0.9V REG_4.SchDoc
size A; SheetNumber: 20; SheetTotal: 20
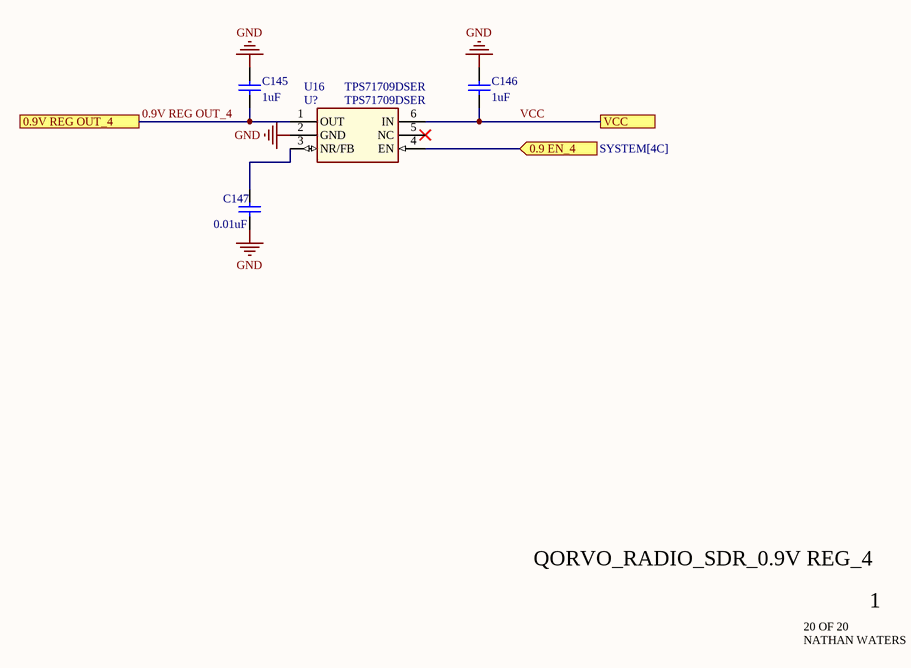
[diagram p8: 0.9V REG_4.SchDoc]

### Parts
C145  CAPACITANCE: 1uF  [0402 CAP_IND_RES]  (hidden comment: GRM155R61H105KE05D)
C146  CAPACITANCE: 1uF  [0402 CAP_IND_RES]  (hidden comment: GRM155R61H105KE05D)
C147  CAPACITANCE: 0.01uF  [0402 CAP_IND_RES]  (hidden comment: GRM155R71C103KA01D)
U16  TPS71709DSER  [TPS71709DSER]

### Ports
0.9 EN_4 (in, see SYSTEM[4C]), 0.9V REG OUT_4 (see SYSTEM[4C], Q HE AA[4C]), VCC (see SYSTEM[4C], 0.9V REG_1[3B], 0.9V REG_2[3B], 0.9V REG_3[3B], 3.3v REG[3B], HE LNA[2A], HE Mixer[3C], I HE AA[1B], I HE LPF[1A], I LE AA[1B], I LE LPF[1A], LE LNA[2A], LE Mixer[3C], Q HE AA[1B], Q HE LPF[1A], Q LE AA[1B], Q LE LPF[1B], SWITCH[3B])

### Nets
GND: C145.2 C146.2 C147.1 U16.2(GND)
0.9V REG OUT_4: C145.1 U16.1(OUT) ; port 0.9V REG OUT_4
HEM EN: U16.4(EN) ; port 0.9 EN_4
VCC: C146.1 U16.6(IN) ; port VCC
NetC147_2: C147.2 U16.3(NR/FB)

Not connected (* = marked no-connect by the designer): U16 5(NC)*

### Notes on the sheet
- QORVO_RADIO_SDR_0.9V REG_4
- 20 OF 20
- 1
- NATHAN WATERS

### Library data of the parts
C145 C146 = 0402_CAP: as C86 on sheet 3.3v REG
C147 = 0402_CAP: as C70 on sheet HE LNA
U16 = TPS71709DSER: as U10 on sheet 0.9V REG_1

## Sheet LE LNA.SchDoc
size A; SheetNumber: 7; SheetTotal: 20
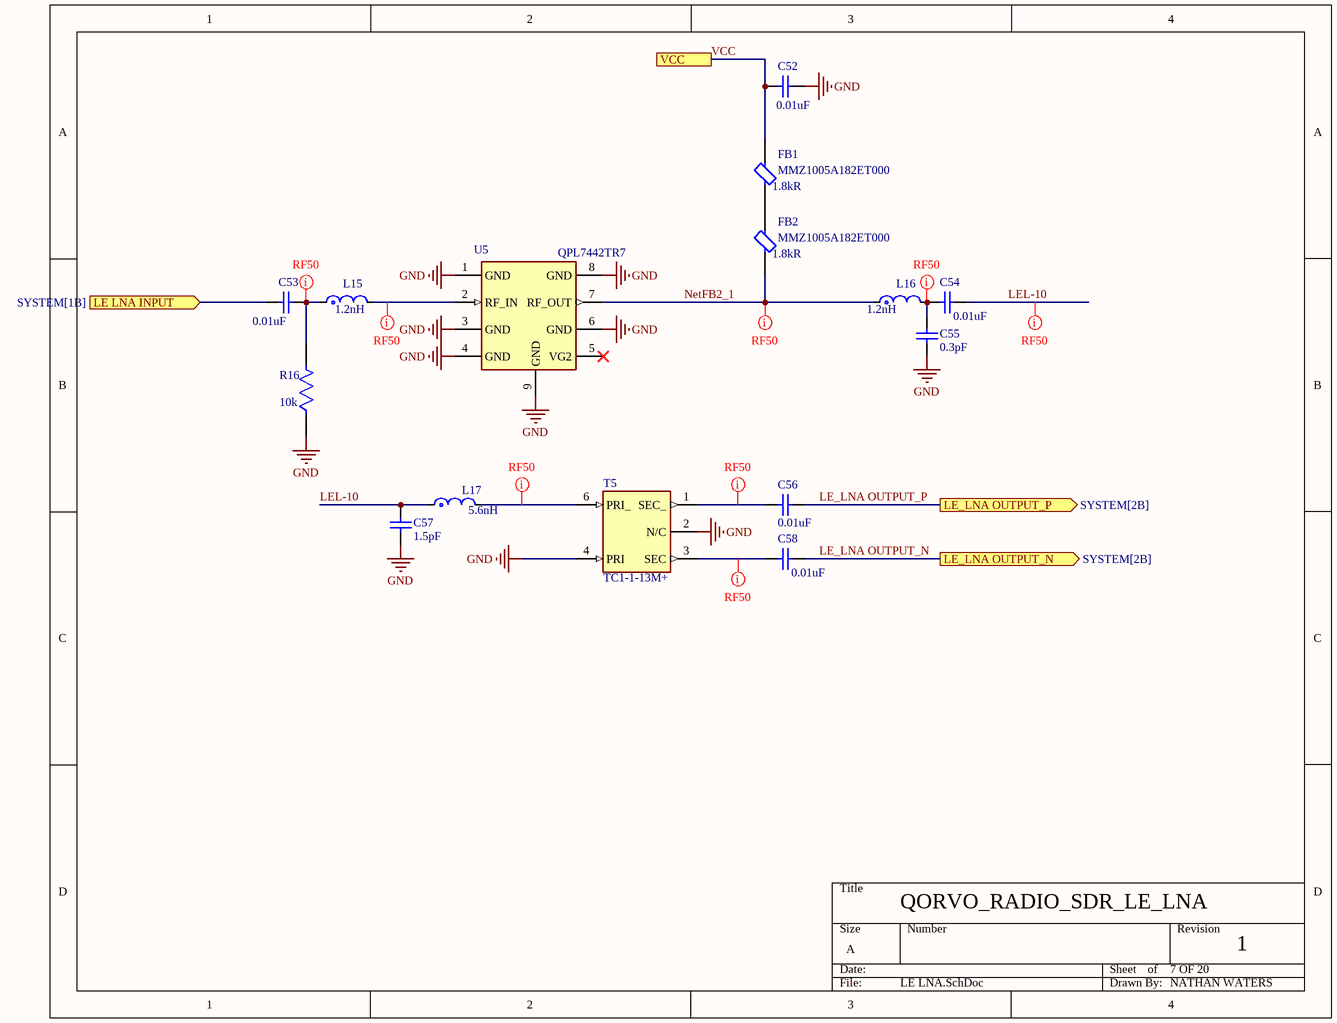
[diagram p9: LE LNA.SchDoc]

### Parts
C52  CAPACITANCE: 0.01uF  [0402 CAP_IND_RES]  (hidden comment: GRM155R71C103KA01D)
C53  CAPACITANCE: 0.01uF  [0402 CAP_IND_RES]  (hidden comment: GRM155R71C103KA01D)
C54  CAPACITANCE: 0.01uF  [0402 CAP_IND_RES]  (hidden comment: GRM155R71C103KA01D)
C55  CAPACITANCE: 0.3pF  [0402 CAP_IND_RES]  (hidden comment: GJM1555C1HR30WB01D)
C56  CAPACITANCE: 0.01uF  [0402 CAP_IND_RES]  (hidden comment: GRM155R71C103KA01D)
C57  CAPACITANCE: 1.5pF  [0402 CAP_IND_RES]  (hidden comment: GJM1555C1H1R5BB01D)
C58  CAPACITANCE: 0.01uF  [0402 CAP_IND_RES]  (hidden comment: GRM155R71C103KA01D)
FB1  MMZ1005A182ET000  Impeadance: 1.8kR  [0402 CAP_IND_RES]
FB2  MMZ1005A182ET000  Impeadance: 1.8kR  [0402 CAP_IND_RES]
L15  Inductance: 1.2nH  [0402 CAP_IND_RES]  (hidden comment: LQG15HS1N2S02D)
L16  Inductance: 1.2nH  [0402 CAP_IND_RES]  (hidden comment: LQG15HS1N2S02D)
L17  Inductance: 5.6nH  [0402 CAP_IND_RES]  (hidden comment: LQG15HS5N6B02D)
R16  Resistance: 10k  [0402 CAP_IND_RES]  (hidden comment: CRCW040210K0FKEDC)
T5  TC1-1-13M+  [TC1-1-13M+]
U5  QPL7442TR7  [QPL7442TR7]

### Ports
LE LNA INPUT (in, see SYSTEM[1B]), LE_LNA OUTPUT_N (out, see SYSTEM[2B]), LE_LNA OUTPUT_P (out, see SYSTEM[2B]), VCC (see SYSTEM[2B], 0.9V REG_1[3B], 0.9V REG_2[3B], 0.9V REG_3[3B], 0.9V REG_4[3B], 3.3v REG[3B], HE LNA[2A], HE Mixer[3C], I HE AA[1B], I HE LPF[1A], I LE AA[1B], I LE LPF[1A], LE Mixer[3C], Q HE AA[1B], Q HE LPF[1A], Q LE AA[1B], Q LE LPF[1B], SWITCH[4B])

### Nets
GND: C52.2 C55.1 C57.1 R16.1 T5.2(N/C) T5.4(PRI) U5.1(GND) U5.3(GND) U5.4(GND) U5.6(GND) U5.8(GND) U5.9(GND)
LE_LNA OUTPUT_N: C58.2 ; port LE_LNA OUTPUT_N
LE_LNA OUTPUT_P: C56.1 ; port LE_LNA OUTPUT_P
LEL-10: C54.2 C57.2 L17.1
NetFB2_1: FB2.1 L16.1 U5.7(RF_OUT)
VCC: C52.1 FB1.2 ; port VCC
NetC53_1: C53.1 ; port LE LNA INPUT
NetC53_2: C53.2 L15.1 R16.2
NetC54_1: C54.1 C55.2 L16.2
NetC56_2: C56.2 T5.1(SEC_)
NetC58_1: C58.1 T5.3(SEC)
NetFB1_1: FB1.1 FB2.2
NetL15_2: L15.2 U5.2(RF_IN)
NetL17_2: L17.2 T5.6(PRI_)

Not connected (* = marked no-connect by the designer): U5 5(VG2)*

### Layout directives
net class RF50: LEL-10, NetC53_2, NetC54_1, NetC56_2, NetC58_1, NetFB2_1, NetL15_2, NetL17_2

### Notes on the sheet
- QORVO_RADIO_SDR_LE_LNA
- 7 OF 20
- 1
- NATHAN WATERS

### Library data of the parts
C52-C54 C56 C58 = 0402_CAP: as C70 on sheet HE LNA
C55 = 0402_CAP: as C73 on sheet HE LNA
C57 = 0402_CAP: Multi-Layer Ceramic Capacitor 1.5pF C0G  ±0.1pF 0402 Paper T/R
FB1 FB2 = 0402_FERRITE_BEADS: as FB3 on sheet HE LNA
L15 L16 = 0402_IND: 1A 1.2nH 70mΩ 0402 Inductors (SMD) ROHS
L17 = 0402_IND: Multilayer type RF Inductor 5.6nH ±0.1nH 0.18Ω 650mA 0402
R16 = 0402_RES: RES 10K OHM 1% 1/16W 0402
T5 = TC1-1-13M+: SMD,3.8x3.8mm RF Misc ICs and Modules ROHS
U5 = QPL7442TR7: Qorvo QPL7442TR7

## Sheet LE Mixer.SchDoc
size A; SheetNumber: 5; SheetTotal: 20
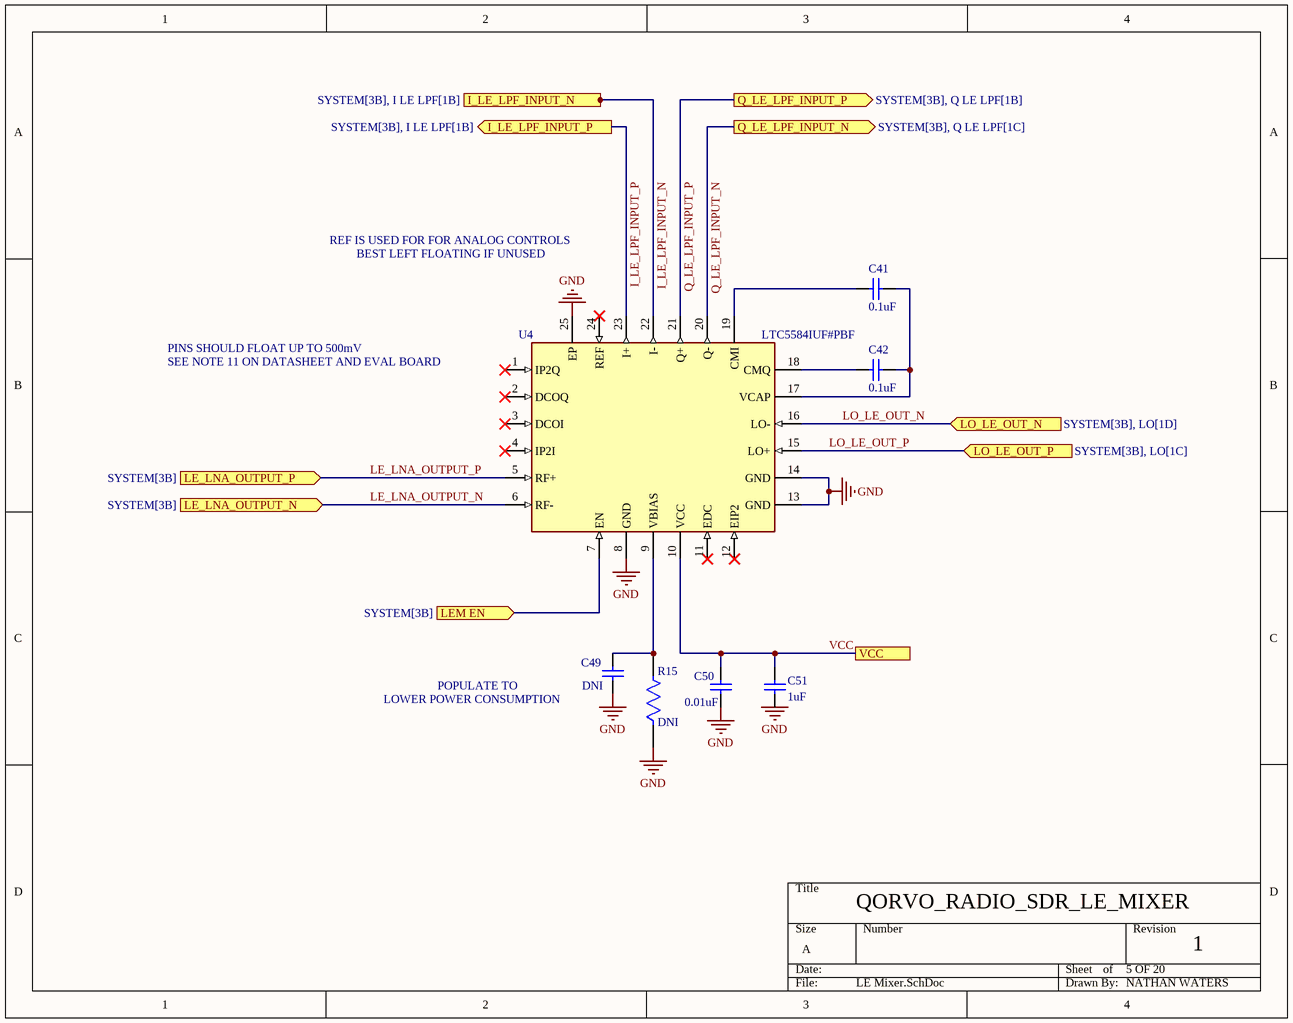
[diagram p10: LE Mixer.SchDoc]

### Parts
C41  CAPACITANCE: 0.1uF  [0402 CAP_IND_RES]  (hidden comment: CL05B104KO5NNNC)
C42  CAPACITANCE: 0.1uF  [0402 CAP_IND_RES]  (hidden comment: CL05B104KO5NNNC)
C49  DNI  [0805_CAP]  (no BOM)
C50  CAPACITANCE: 0.01uF  [0402 CAP_IND_RES]  (hidden comment: GRM155R71C103KA01D)
C51  CAPACITANCE: 1uF  [0402 CAP_IND_RES]  (hidden comment: GRM155R61H105KE05D)
R15  0402_RES  [0402 CAP_IND_RES]  (value not drawn)  (no BOM)
U4  LTC5584IUF#PBF  [LTC5584/LTC5585]

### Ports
I_LE_LPF_INPUT_N (out, see SYSTEM[3B], I LE LPF[1B]), I_LE_LPF_INPUT_P (out, see SYSTEM[3B], I LE LPF[1B]), LE_LNA_OUTPUT_N (in, see SYSTEM[3B]), LE_LNA_OUTPUT_P (in, see SYSTEM[3B]), LEM EN (in, see SYSTEM[3B]), LO_LE_OUT_N (in, see SYSTEM[3B], LO[1D]), LO_LE_OUT_P (in, see SYSTEM[3B], LO[1C]), Q_LE_LPF_INPUT_N (out, see SYSTEM[3B], Q LE LPF[1C]), Q_LE_LPF_INPUT_P (out, see SYSTEM[3B], Q LE LPF[1B]), VCC (see SYSTEM[3B], 0.9V REG_1[3B], 0.9V REG_2[3B], 0.9V REG_3[3B], 0.9V REG_4[3B], 3.3v REG[3B], HE LNA[2A], HE Mixer[3C], I HE AA[1B], I HE LPF[1A], I LE AA[1B], I LE LPF[1A], LE LNA[2A], Q HE AA[1B], Q HE LPF[1A], Q LE AA[1B], Q LE LPF[1B], SWITCH[4B])

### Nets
GND: C49.1 C50.1 R15.1 U4.8(GND) U4.13(GND) U4.14(GND) U4.25(EP)
I_LE_LPF_INPUT_N: U4.22(I-) ; port I_LE_LPF_INPUT_N
I_LE_LPF_INPUT_P: U4.23(I+) ; port I_LE_LPF_INPUT_P
LE_LNA_OUTPUT_N: U4.6(RF-) ; port LE_LNA_OUTPUT_N  [project net LE_LNA OUTPUT_N]
LE_LNA_OUTPUT_P: U4.5(RF+) ; port LE_LNA_OUTPUT_P  [project net LE_LNA OUTPUT_P]
LEM EN: U4.7(EN) ; port LEM EN
LO_LE_OUT_N: U4.16(LO-) ; port LO_LE_OUT_N
LO_LE_OUT_P: U4.15(LO+) ; port LO_LE_OUT_P
Q_LE_LPF_INPUT_N: U4.20(Q-) ; port Q_LE_LPF_INPUT_N
Q_LE_LPF_INPUT_P: U4.21(Q+) ; port Q_LE_LPF_INPUT_P
VCC: C50.2 C51.2 U4.10(VCC) ; port VCC
NetC41_1: C41.1 U4.19(CMI)
NetC41_2: C41.2 C42.2 U4.17(VCAP)
NetC42_1: C42.1 U4.18(CMQ)
NetC49_2: C49.2 R15.2 U4.9(VBIAS)

Not connected (* = marked no-connect by the designer): C51 1; U4 1(IP2Q)* 2(DCOQ)* 3(DCOI)* 4(IP2I)* 11(EDC)* 12(EIP2)* 24(REF)*

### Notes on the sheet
- REF IS USED FOR FOR ANALOG CONTROLS
- BEST LEFT FLOATING IF UNUSED
- PINS SHOULD FLOAT UP TO 500mV
- SEE NOTE 11 ON DATASHEET AND EVAL BOARD
- LOWER POWER CONSUMPTION
- POPULATE TO
- QORVO_RADIO_SDR_LE_MIXER
- 5 OF 20
- 1
- NATHAN WATERS
- Labels drawn without touching a wire or pin: GND

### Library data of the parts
C41 C42 = 0402_CAP: as C150 on sheet SWITCH
C49 = 0805_CAP
C50 = 0402_CAP: as C70 on sheet HE LNA
C51 = 0402_CAP: as C86 on sheet 3.3v REG
R15 = 0402_RES: DNI
U4 = LTC5584IUF#PBF: 30MHz~1.4GHz 9.9dB 5.4dB QFN-24-EP(4x4) RF Modulators and Demodulators ROHS; Manufacturer_Name: Analog Devices

## Sheet LO.SchDoc
size A; SheetNumber: 4; SheetTotal: 20
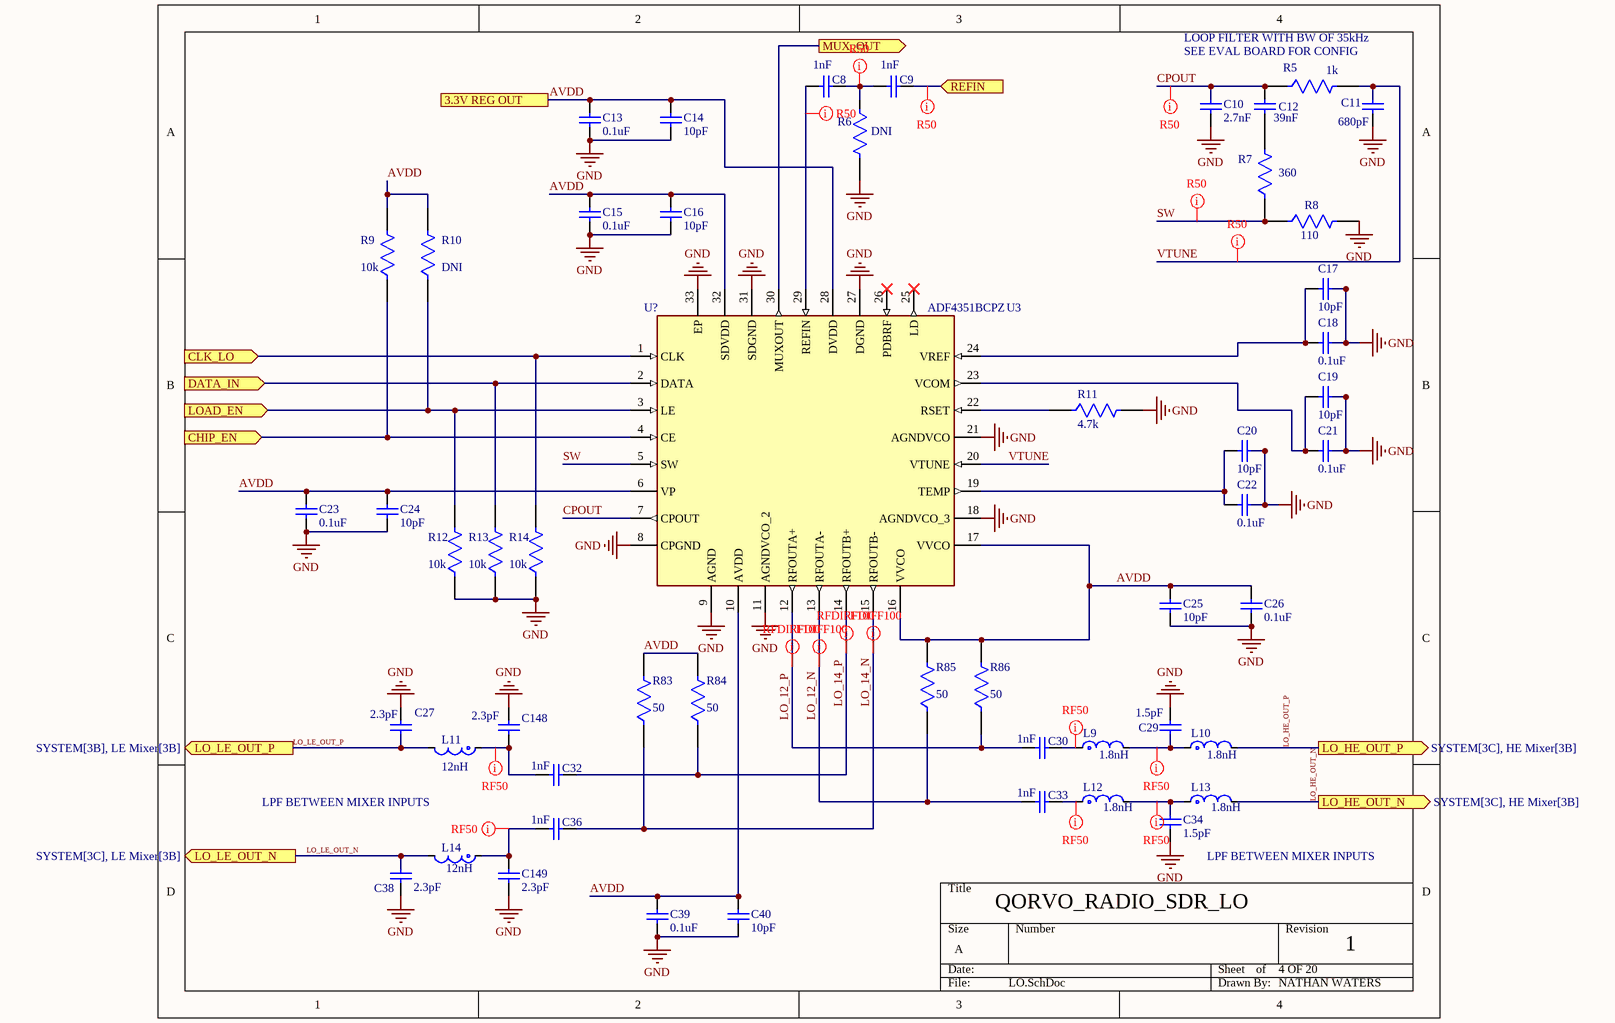
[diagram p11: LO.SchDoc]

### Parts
C8  Capacitance: 1nF  [0402 CAP_IND_RES]  (hidden comment: GCM1555C1H102FA16D)
C9  Capacitance: 1nF  [0402 CAP_IND_RES]  (hidden comment: GCM1555C1H102FA16D)
C10  CAPACITANCE: 2.7nF  [0402 CAP_IND_RES]  (hidden comment: GCM155R71H272KA37D)
C11  CAPACITANCE: 680pF  [0402 CAP_IND_RES]  (hidden comment: GCM1555C1H681JA16D)
C12  CAPACITANCE: 39nF  [0402 CAP_IND_RES]  (hidden comment: GCM1555C1H390JA16D)
C13  CAPACITANCE: 0.1uF  [0402 CAP_IND_RES]  (hidden comment: CL05B104KO5NNNC)
C14  CAPACITANCE: 10pF  [0402 CAP_IND_RES]  (hidden comment: GJM1555C1H100JB01D)
C15  CAPACITANCE: 0.1uF  [0402 CAP_IND_RES]  (hidden comment: CL05B104KO5NNNC)
C16  CAPACITANCE: 10pF  [0402 CAP_IND_RES]  (hidden comment: GJM1555C1H100JB01D)
C17  CAPACITANCE: 10pF  [0402 CAP_IND_RES]  (hidden comment: GJM1555C1H100JB01D)
C18  CAPACITANCE: 0.1uF  [0402 CAP_IND_RES]  (hidden comment: CL05B104KO5NNNC)
C19  CAPACITANCE: 10pF  [0402 CAP_IND_RES]  (hidden comment: GJM1555C1H100JB01D)
C20  CAPACITANCE: 10pF  [0402 CAP_IND_RES]  (hidden comment: GJM1555C1H100JB01D)
C21  CAPACITANCE: 0.1uF  [0402 CAP_IND_RES]  (hidden comment: CL05B104KO5NNNC)
C22  CAPACITANCE: 0.1uF  [0402 CAP_IND_RES]  (hidden comment: CL05B104KO5NNNC)
C23  CAPACITANCE: 0.1uF  [0402 CAP_IND_RES]  (hidden comment: CL05B104KO5NNNC)
C24  CAPACITANCE: 10pF  [0402 CAP_IND_RES]  (hidden comment: GJM1555C1H100JB01D)
C25  CAPACITANCE: 10pF  [0402 CAP_IND_RES]  (hidden comment: GJM1555C1H100JB01D)
C26  CAPACITANCE: 0.1uF  [0402 CAP_IND_RES]  (hidden comment: CL05B104KO5NNNC)
C27  CAPACITANCE: 2.3pF  [0402 CAP_IND_RES]  (hidden comment: CQ0402BRNPO9BN2R3)
C29  CAPACITANCE: 1.5pF  [0402 CAP_IND_RES]  (hidden comment: GJM1555C1H1R5BB01D)
C30  CAPACITANCE: 1nF  [0402 CAP_IND_RES]  (hidden comment: GRM1555C1H102JA01D)
C32  CAPACITANCE: 1nF  [0402 CAP_IND_RES]  (hidden comment: GRM1555C1H102JA01D)
C33  CAPACITANCE: 1nF  [0402 CAP_IND_RES]  (hidden comment: GRM1555C1H102JA01D)
C34  CAPACITANCE: 1.5pF  [0402 CAP_IND_RES]  (hidden comment: GJM1555C1H1R5BB01D)
C36  CAPACITANCE: 1nF  [0402 CAP_IND_RES]  (hidden comment: GRM1555C1H102JA01D)
C38  CAPACITANCE: 2.3pF  [0402 CAP_IND_RES]  (hidden comment: CQ0402BRNPO9BN2R3)
C39  CAPACITANCE: 0.1uF  [0402 CAP_IND_RES]  (hidden comment: CL05B104KO5NNNC)
C40  CAPACITANCE: 10pF  [0402 CAP_IND_RES]  (hidden comment: GJM1555C1H100JB01D)
C148  CAPACITANCE: 2.3pF  [0402 CAP_IND_RES]  (hidden comment: CQ0402BRNPO9BN2R3)
C149  CAPACITANCE: 2.3pF  [0402 CAP_IND_RES]  (hidden comment: CQ0402BRNPO9BN2R3)
L9  Inductance: 1.8nH  [0402 CAP_IND_RES]  (hidden comment: LQG15HS1N8S02D)
L10  Inductance: 1.8nH  [0402 CAP_IND_RES]  (hidden comment: LQG15HS1N8S02D)
L11  Inductance: 12nH  [0402 CAP_IND_RES]  (hidden comment: SDCL1005C12NJTDF)
L12  Inductance: 1.8nH  [0402 CAP_IND_RES]  (hidden comment: LQG15HS1N8S02D)
L13  Inductance: 1.8nH  [0402 CAP_IND_RES]  (hidden comment: LQG15HS1N8S02D)
L14  Inductance: 12nH  [0402 CAP_IND_RES]  (hidden comment: SDCL1005C12NJTDF)
R5  Resistance: 1k  [0402 CAP_IND_RES]  (hidden comment: RC0402JR-071KL)
R6  Resistance: DNI  [0603_CAP]  (hidden comment: CRCW040251R0FKED)
R7  Resistance: 360  [0402 CAP_IND_RES]  (hidden comment: RC0402FR-07360RL)
R8  Resistance: 110  [0402 CAP_IND_RES]  (hidden comment: CRCW0402110RFKED)
R9  RESISTANCE: 10k  [0402 CAP_IND_RES]  (hidden comment: CRCW040210K0FKEDC)
R10  DNI  [0402 CAP_IND_RES]  (no BOM)
R11  Resistance: 4.7k  [0402 CAP_IND_RES]  (hidden comment: 0402WGF4701TCE)
R12  Resistance: 10k  [0402 CAP_IND_RES]  (hidden comment: CRCW040210K0FKEDC)
R13  Resistance: 10k  [0402 CAP_IND_RES]  (hidden comment: CRCW040210K0FKEDC)
R14  Resistance: 10k  [0402 CAP_IND_RES]  (hidden comment: CRCW040210K0FKEDC)
R83  Resistance: 50  [0402 CAP_IND_RES]  (hidden comment: AC0402JR-0750RL)
R84  Resistance: 50  [0402 CAP_IND_RES]  (hidden comment: AC0402JR-0750RL)
R85  Resistance: 50  [0402 CAP_IND_RES]  (hidden comment: AC0402JR-0750RL)
R86  Resistance: 50  [0402 CAP_IND_RES]  (hidden comment: AC0402JR-0750RL)
U3  ADF4351BCPZ  [ADF4351BCPZ]  (value not drawn)

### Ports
3.3V REG OUT (see SYSTEM[2C], 3.3v REG[2B]), CHIP_EN (in, see SYSTEM[2B]), CLK_LO (in, see SYSTEM[2B]), DATA_IN (in, see SYSTEM[2B]), LO_HE_OUT_N (out, see SYSTEM[3C], HE Mixer[3B]), LO_HE_OUT_P (out, see SYSTEM[3C], HE Mixer[3B]), LO_LE_OUT_N (out, see SYSTEM[3C], LE Mixer[3B]), LO_LE_OUT_P (out, see SYSTEM[3B], LE Mixer[3B]), LOAD_EN (in, see SYSTEM[2B]), MUX_OUT (out, see SYSTEM[3C]), REFIN (in, see SYSTEM[2B])

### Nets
GND: C10.1 C11.1 C13.1 C14.1 C15.1 C16.1 C17.2 C18.2 C19.2 C20.2 C21.2 C22.2 C23.1 C24.1 C25.1 C26.1 C27.2 C29.2 C34.1 C38.1 C39.1 C40.1 C148.2 C149.2 R6.2 R8.2 R11.2 R12.1 R13.1 R14.1 U3.8(CPGND) U3.9(AGND) U3.11(AGNDVCO_2) U3.18(AGNDVCO_3) U3.21(AGNDVCO) U3.27(DGND) U3.31(SDGND) U3.33(EP)
AVDD: C13.2 C14.2 C15.2 C16.2 C23.2 C24.2 C25.2 C26.2 C39.2 C40.2 R9.2 R10.2 R83.2 R84.2 R85.2 R86.2 U3.6(VP) U3.10(AVDD) U3.16(VVCO) U3.17(VVCO) U3.28(DVDD) U3.32(SDVDD) ; port 3.3V REG OUT
CHIP_EN: R9.1 U3.4(CE) ; port CHIP_EN
CPOUT: C10.2 C12.1 R5.1 U3.7(CPOUT)
LO_12_N: C33.1 R85.1 U3.13(RFOUTA-)
LO_12_P: C30.1 R86.1 U3.12(RFOUTA+)
LO_14_N: C36.2 R83.1 U3.15(RFOUTB-)
LO_14_P: C32.2 R84.1 U3.14(RFOUTB+)
LO_HE_OUT_N: L13.2 ; port LO_HE_OUT_N
LO_HE_OUT_P: L10.2 ; port LO_HE_OUT_P
LO_LE_OUT_N: C38.2 L14.2 ; port LO_LE_OUT_N
LO_LE_OUT_P: C27.1 L11.2 ; port LO_LE_OUT_P
LOAD_EN: R10.1 R12.2 U3.3(LE) ; port LOAD_EN
MOSI: R13.2 U3.2(DATA) ; port DATA_IN
MUX_OUT: U3.30(MUXOUT) ; port MUX_OUT
REFIN: C9.2 ; port REFIN
SCK: R14.2 U3.1(CLK) ; port CLK_LO
SW: R7.1 R8.1 U3.5(SW)
VTUNE: C11.2 R5.2 U3.20(VTUNE)
NetC8_1: C8.1 U3.29(REFIN)
NetC8_2: C8.2 C9.1 R6.1
NetC12_2: C12.2 R7.2
NetC17_1: C17.1 C18.1 U3.24(VREF)
NetC19_1: C19.1 C21.1 U3.23(VCOM)
NetC20_1: C20.1 C22.1 U3.19(TEMP)
NetC29_1: C29.1 L9.2 L10.1
NetC30_2: C30.2 L9.1
NetC32_1: C32.1 C148.1 L11.1
NetC33_2: C33.2 L12.1
NetC34_2: C34.2 L12.2 L13.1
NetC36_1: C36.1 C149.1 L14.1
NetR11_1: R11.1 U3.22(RSET)

Not connected (* = marked no-connect by the designer): U3 25(LD)* 26(PDBRF)*

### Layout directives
differential pair; differential pair class RFDIFF100: LO_12_N, LO_12_P, LO_14_N, LO_14_P
net class R50: CPOUT, NetC8_1, NetC8_2, REFIN, SW, VTUNE
net class RF50: NetC29_1, NetC30_2, NetC32_1, NetC33_2, NetC34_2, NetC36_1

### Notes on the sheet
- LOOP FILTER WITH BW OF 35kHz
- SEE EVAL BOARD FOR CONFIG
- LPF BETWEEN MIXER INPUTS
- QORVO_RADIO_SDR_LO
- 4 OF 20
- 1
- NATHAN WATERS

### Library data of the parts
C8 C9 = 0805_CAP: 50V 1nF C0G ±1% 0402 Multilayer Ceramic Capacitors MLCC - SMD/SMT ROHS
C10 = 0402_CAP: 50V 2.7nF X7R ±10% 0402 Multilayer Ceramic Capacitors MLCC - SMD/SMT ROHS
C11 = 0402_CAP: Ceramic Capacitor for Automotive 680pF ±5% 50VDC C0G 0402 Paper T/R
C12 = 0402_CAP: 50V 39pF C0G ±5% 0402 Multilayer Ceramic Capacitors MLCC - SMD/SMT ROHS
C13 C15 C18 C21-C23 C26 C39 = 0402_CAP: as C150 on sheet SWITCH
C14 C16 C17 C19 C20 C24 C25 C40 = 0402_CAP: Multi-Layer Ceramic Capacitor 10pF C0G  ±5% 0402 Paper T/R
C27 C38 C148 C149 = 0402_CAP: 50V 2.3pF C0G 0402 Multilayer Ceramic Capacitors MLCC - SMD/SMT ROHS
C29 C34 = 0402_CAP: 50V 1.5pF C0G 0402 Multilayer Ceramic Capacitors MLCC - SMD/SMT ROHS
C30 C32 C33 C36 = 0402_CAP: 50V 1nF C0G ±5% 0402 Multilayer Ceramic Capacitors MLCC - SMD/SMT ROHS
L9 L10 L12 L13 = 0402_IND: 950mA 1.8nH 80mΩ 0402 Inductors (SMD) ROHS
L11 L14 = 0402_IND: 300mA 12nH ±5% 500mΩ 0402 Inductors (SMD) ROHS
R5 = 0402_RES: 62.5mW Thick Film Resistors 50V ±100ppm/℃ ±5% 1kΩ 0402 Chip Resistor - Surface Mount ROHS
R6 = 0402_RES: DNI, DATASHEET SAYS 51-OHM, SHOULD BE 50-OHM TO GND DUE TO TRACE
R7 = 0402_RES: 62.5mW Thick Film Resistors 50V ±100ppm/℃ ±1% 360Ω 0402 Chip Resistor - Surface Mount ROHS
R8 = 0402_RES: RES Thick Film, 110Ω, 1%, 0.063W, 100ppm/°C, 0402
R9 R12-R14 = 0402_RES: RES 10K OHM 1% 1/16W 0402
R10 = 0402_RES
R11 = 0402_RES: RES Thick Film, 4.7kΩ, 1%, 0.063W, 100ppm/°C, 0402
R83-R86 = 0402_RES: 62.5mW Thick Film Resistors 50V ±100ppm/℃ ±5% 50Ω 0402 Chip Resistor - Surface Mount ROHS
U3 = ADF4351BCPZ: 4.4GHz LFCSP-32(5x5) Clock Generators, PLLs, Frequency Synthesizers ROHS; Manufacturer_Name: Analog Devices

## Sheet HE Mixer.SchDoc
size A; SheetNumber: 6; SheetTotal: 20
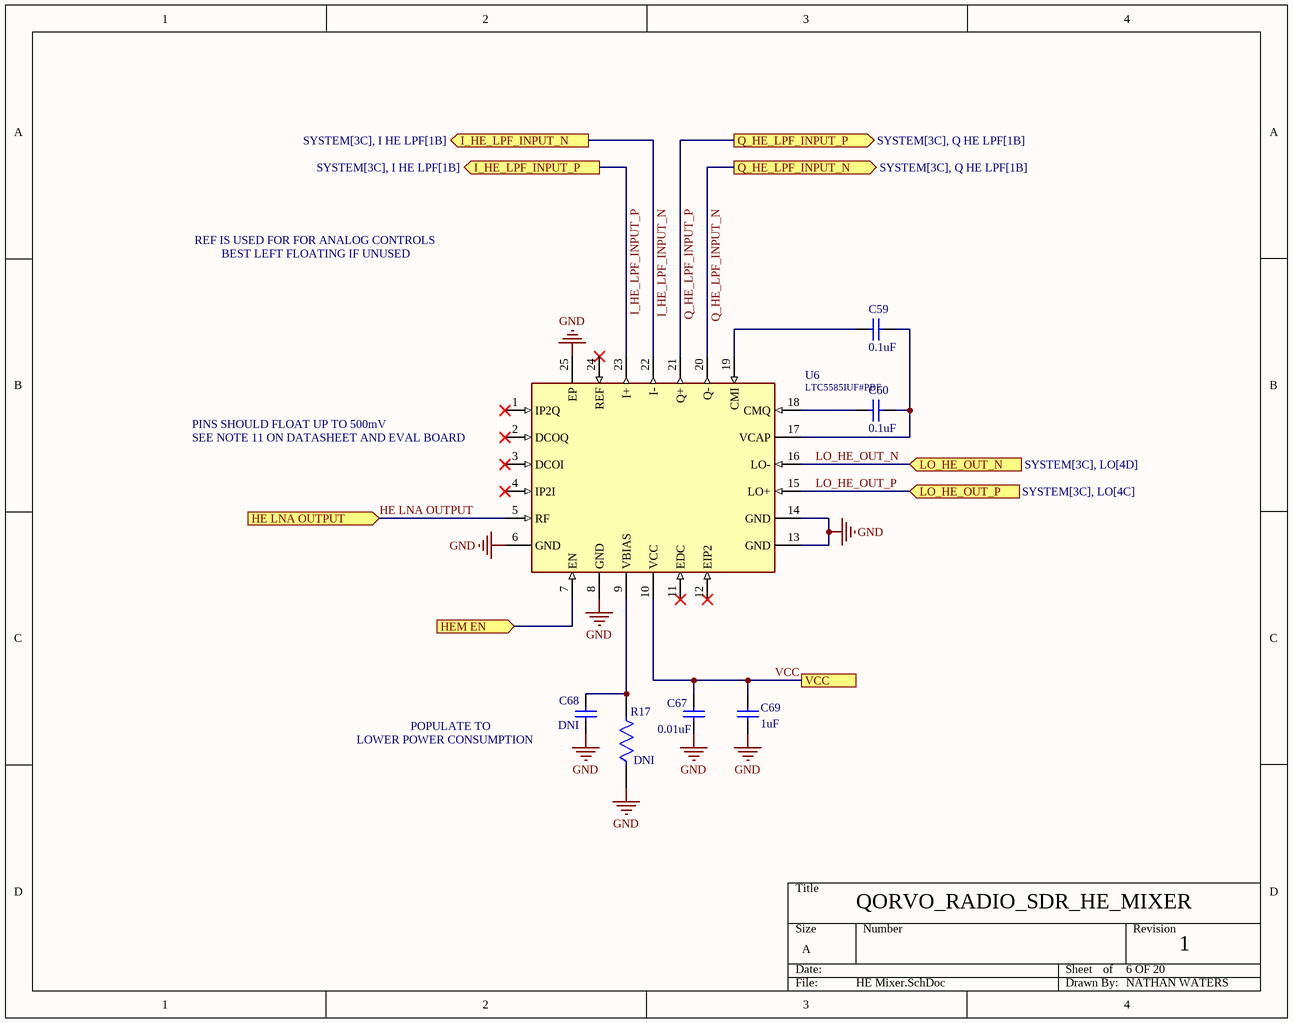
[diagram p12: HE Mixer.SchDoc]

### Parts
C59  CAPACITANCE: 0.1uF  [0402 CAP_IND_RES]  (hidden comment: CL05B104KO5NNNC)
C60  CAPACITANCE: 0.1uF  [0402 CAP_IND_RES]  (hidden comment: CL05B104KO5NNNC)
C67  CAPACITANCE: 0.01uF  [0402 CAP_IND_RES]  (hidden comment: GRM155R71C103KA01D)
C68  0805_CAP  [0805_CAP]  (value not drawn)  (no BOM)
C69  CAPACITANCE: 1uF  [0402 CAP_IND_RES]  (hidden comment: GRM155R61H105KE05D)
R17  0402_RES  [0402 CAP_IND_RES]  (value not drawn)  (no BOM)
U6  LTC5585IUF#PBF  [LTC5584/LTC5585]

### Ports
HE LNA OUTPUT (in, see SYSTEM[3C], HE LNA[4B]), HEM EN (in, see SYSTEM[3C]), I_HE_LPF_INPUT_N (out, see SYSTEM[3C], I HE LPF[1B]), I_HE_LPF_INPUT_P (out, see SYSTEM[3C], I HE LPF[1B]), LO_HE_OUT_N (in, see SYSTEM[3C], LO[4D]), LO_HE_OUT_P (in, see SYSTEM[3C], LO[4C]), Q_HE_LPF_INPUT_N (out, see SYSTEM[3C], Q HE LPF[1B]), Q_HE_LPF_INPUT_P (out, see SYSTEM[3C], Q HE LPF[1B]), VCC (see SYSTEM[3C], 0.9V REG_1[3B], 0.9V REG_2[3B], 0.9V REG_3[3B], 0.9V REG_4[3B], 3.3v REG[3B], HE LNA[2A], I HE AA[1B], I HE LPF[1A], I LE AA[1B], I LE LPF[1A], LE LNA[2A], LE Mixer[3C], Q HE AA[1B], Q HE LPF[1A], Q LE AA[1B], Q LE LPF[1B], SWITCH[4B])

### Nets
GND: C67.1 C68.1 C69.1 R17.1 U6.6(GND) U6.8(GND) U6.13(GND) U6.14(GND) U6.25(EP)
HE LNA OUTPUT: U6.5(RF) ; port HE LNA OUTPUT
HEM EN: U6.7(EN) ; port HEM EN
I_HE_LPF_INPUT_N: U6.22(I-) ; port I_HE_LPF_INPUT_N
I_HE_LPF_INPUT_P: U6.23(I+) ; port I_HE_LPF_INPUT_P
LO_HE_OUT_N: U6.16(LO-) ; port LO_HE_OUT_N
LO_HE_OUT_P: U6.15(LO+) ; port LO_HE_OUT_P
Q_HE_LPF_INPUT_N: U6.20(Q-) ; port Q_HE_LPF_INPUT_N
Q_HE_LPF_INPUT_P: U6.21(Q+) ; port Q_HE_LPF_INPUT_P
VCC: C67.2 C69.2 U6.10(VCC) ; port VCC
NetC59_1: C59.1 U6.19(CMI)
NetC59_2: C59.2 C60.2 U6.17(VCAP)
NetC60_1: C60.1 U6.18(CMQ)
NetC68_2: C68.2 R17.2 U6.9(VBIAS)

Not connected (* = marked no-connect by the designer): U6 1(IP2Q)* 2(DCOQ)* 3(DCOI)* 4(IP2I)* 11(EDC)* 12(EIP2)* 24(REF)*

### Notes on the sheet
- REF IS USED FOR FOR ANALOG CONTROLS
- BEST LEFT FLOATING IF UNUSED
- PINS SHOULD FLOAT UP TO 500mV
- SEE NOTE 11 ON DATASHEET AND EVAL BOARD
- LOWER POWER CONSUMPTION
- POPULATE TO
- QORVO_RADIO_SDR_HE_MIXER
- 6 OF 20
- 1
- NATHAN WATERS

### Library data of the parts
C59 C60 = 0402_CAP: as C150 on sheet SWITCH
C67 = 0402_CAP: as C70 on sheet HE LNA
C68 = 0805_CAP: DNI
C69 = 0402_CAP: as C86 on sheet 3.3v REG
R17 = 0402_RES: DNI
U6 = LTC5585IUF#PBF: 400MHz~4GHz 12.7dB 2.4dB QFN-24-EP(4x4)  RF Modulators and Demodulators ROHS; Manufacturer_Name: Analog Devices

## Sheet I LE LPF.SchDoc
size A; SheetNumber: 9; SheetTotal: 20
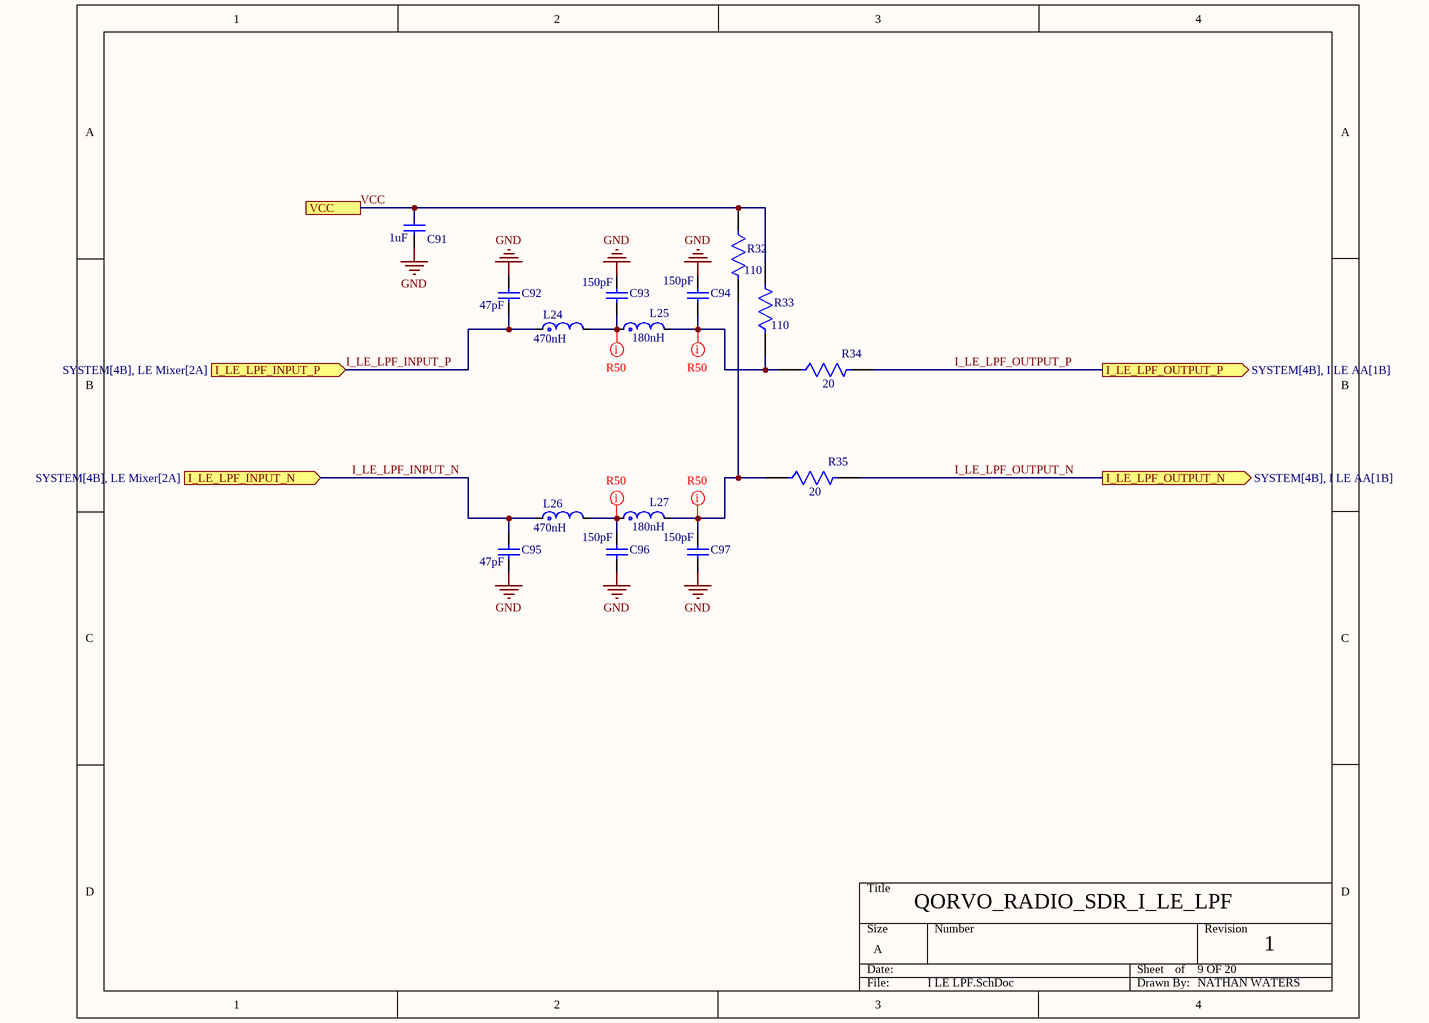
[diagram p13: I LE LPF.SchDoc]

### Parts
C91  CAPACITANCE: 1uF  [0402 CAP_IND_RES]  (hidden comment: GRM155R61H105KE05D)
C92  CAPACITANCE: 47pF  [0402 CAP_IND_RES]  (hidden comment: GJM1555C1H470FB01D)
C93  CAPACITANCE: 150pF  [0603_CAP]  (hidden comment: CC0603JRNPO9BN151)
C94  CAPACITANCE: 150pF  [0603_CAP]  (hidden comment: CC0603JRNPO9BN151)
C95  CAPACITANCE: 47pF  [0402 CAP_IND_RES]  (hidden comment: GJM1555C1H470FB01D)
C96  CAPACITANCE: 150pF  [0603_CAP]  (hidden comment: CC0603JRNPO9BN151)
C97  CAPACITANCE: 150pF  [0603_CAP]  (hidden comment: CC0603JRNPO9BN151)
L24  INDUCTANCE: 470nH  [0402 CAP_IND_RES]  (hidden comment: MWSD1005FR47JTM01)
L25  INDUCTANCE: 180nH  [0402 CAP_IND_RES]  (hidden comment: SDCL1005CR18JTDF)
L26  INDUCTANCE: 470nH  [0402 CAP_IND_RES]  (hidden comment: MWSD1005FR47JTM01)
L27  INDUCTANCE: 180nH  [0402 CAP_IND_RES]  (hidden comment: SDCL1005CR18JTDF)
R32  RESISTANCE: 110  [0402 CAP_IND_RES]  (hidden comment: CRCW0402110RFKED)
R33  RESISTANCE: 110  [0402 CAP_IND_RES]  (hidden comment: CRCW0402110RFKED)
R34  RESISTANCE: 20  [0402 CAP_IND_RES]  (hidden comment: CRCW040220R0FKED)
R35  RESISTANCE: 20  [0402 CAP_IND_RES]  (hidden comment: CRCW040220R0FKED)

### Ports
I_LE_LPF_INPUT_N (in, see SYSTEM[4B], LE Mixer[2A]), I_LE_LPF_INPUT_P (in, see SYSTEM[4B], LE Mixer[2A]), I_LE_LPF_OUTPUT_N (out, see SYSTEM[4B], I LE AA[1B]), I_LE_LPF_OUTPUT_P (out, see SYSTEM[4B], I LE AA[1B]), VCC (see SYSTEM[4B], 0.9V REG_1[3B], 0.9V REG_2[3B], 0.9V REG_3[3B], 0.9V REG_4[3B], 3.3v REG[3B], HE LNA[2A], HE Mixer[3C], I HE AA[1B], I HE LPF[1A], I LE AA[1B], LE LNA[2A], LE Mixer[3C], Q HE AA[1B], Q HE LPF[1A], Q LE AA[1B], Q LE LPF[1B], SWITCH[4B])

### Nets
GND: C91.1 C92.2 C93.2 C94.2 C95.1 C96.1 C97.1
I_LE_LPF_INPUT_N: C95.2 L26.1 ; port I_LE_LPF_INPUT_N
I_LE_LPF_INPUT_P: C92.1 L24.1 ; port I_LE_LPF_INPUT_P
I_LE_LPF_OUTPUT_N: R35.2 ; port I_LE_LPF_OUTPUT_N
I_LE_LPF_OUTPUT_P: R34.2 ; port I_LE_LPF_OUTPUT_P
VCC: C91.2 R32.1 R33.2 ; port VCC
NetC93_1: C93.1 L24.2 L25.1
NetC94_1: C94.1 L25.2 R33.1 R34.1
NetC96_2: C96.2 L26.2 L27.1
NetC97_2: C97.2 L27.2 R32.2 R35.1

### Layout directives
net class R50: NetC93_1, NetC94_1, NetC96_2, NetC97_2

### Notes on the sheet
- QORVO_RADIO_SDR_I_LE_LPF
- 9 OF 20
- 1
- NATHAN WATERS

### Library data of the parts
C91 = 0402_CAP: as C86 on sheet 3.3v REG
C92 C95 = 0402_CAP: 50V 47pF null ±1% 0402  Multilayer Ceramic Capacitors MLCC - SMD/SMT ROHS
C93 C94 C96 C97 = 0603_CAP: 50V 150pF NP0 ±5% 0603 Multilayer Ceramic Capacitors MLCC - SMD/SMT ROHS
L24 L26 = 0402_IND: 350mA 470nH ±5% 660mΩ 0402  Inductors (SMD) ROHS
L25 L27 = 0402_IND: 100mA 180nH ±5% 3.7Ω 0402 Inductors (SMD) ROHS
R32 R33 = 0402_RES: RESISTOR, RES Thick Film, 110Ω, 1%, 0.063W, 100ppm/°C, 0402
R34 R35 = 0402_RES: RESISTOR, RES Thick Film, 20Ω, 1%, 0.063W, 100ppm/°C, 0402

## Sheet Q LE LPF.SchDoc
size A; SheetNumber: 10; SheetTotal: 20
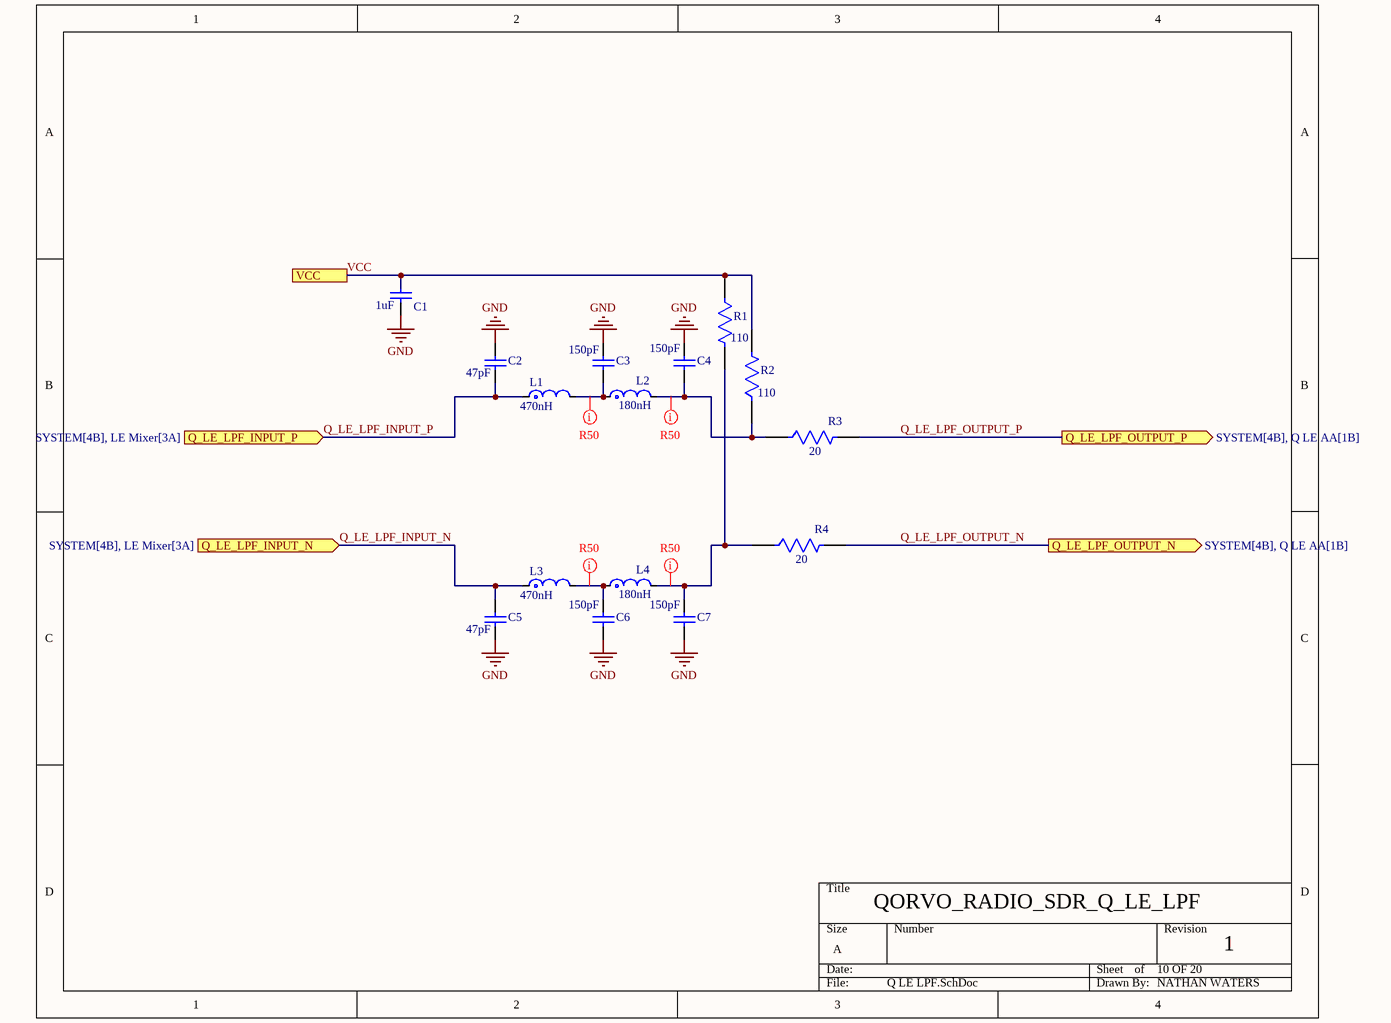
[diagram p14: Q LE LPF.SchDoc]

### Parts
C1  CAPACITANCE: 1uF  [0402 CAP_IND_RES]  (hidden comment: GRM155R61H105KE05D)
C2  CAPACITANCE: 47pF  [0402 CAP_IND_RES]  (hidden comment: GJM1555C1H470FB01D)
C3  CAPACITANCE: 150pF  [0603_CAP]  (hidden comment: CC0603JRNPO9BN151)
C4  CAPACITANCE: 150pF  [0603_CAP]  (hidden comment: CC0603JRNPO9BN151)
C5  CAPACITANCE: 47pF  [0402 CAP_IND_RES]  (hidden comment: GJM1555C1H470FB01D)
C6  CAPACITANCE: 150pF  [0603_CAP]  (hidden comment: CC0603JRNPO9BN151)
C7  CAPACITANCE: 150pF  [0603_CAP]  (hidden comment: CC0603JRNPO9BN151)
L1  INDUCTANCE: 470nH  [0402 CAP_IND_RES]  (hidden comment: MWSD1005FR47JTM01)
L2  INDUCTANCE: 180nH  [0402 CAP_IND_RES]  (hidden comment: SDCL1005CR18JTDF)
L3  INDUCTANCE: 470nH  [0402 CAP_IND_RES]  (hidden comment: MWSD1005FR47JTM01)
L4  INDUCTANCE: 180nH  [0402 CAP_IND_RES]  (hidden comment: SDCL1005CR18JTDF)
R1  RESISTANCE: 110  [0402 CAP_IND_RES]  (hidden comment: CRCW0402110RFKED)
R2  RESISTANCE: 110  [0402 CAP_IND_RES]  (hidden comment: CRCW0402110RFKED)
R3  RESISTANCE: 20  [0402 CAP_IND_RES]  (hidden comment: CRCW040220R0FKED)
R4  RESISTANCE: 20  [0402 CAP_IND_RES]  (hidden comment: CRCW040220R0FKED)

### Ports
Q_LE_LPF_INPUT_N (in, see SYSTEM[4B], LE Mixer[3A]), Q_LE_LPF_INPUT_P (in, see SYSTEM[4B], LE Mixer[3A]), Q_LE_LPF_OUTPUT_N (out, see SYSTEM[4B], Q LE AA[1B]), Q_LE_LPF_OUTPUT_P (out, see SYSTEM[4B], Q LE AA[1B]), VCC (see SYSTEM[4B], 0.9V REG_1[3B], 0.9V REG_2[3B], 0.9V REG_3[3B], 0.9V REG_4[3B], 3.3v REG[3B], HE LNA[2A], HE Mixer[3C], I HE AA[1B], I HE LPF[1A], I LE AA[1B], I LE LPF[1A], LE LNA[2A], LE Mixer[3C], Q HE AA[1B], Q HE LPF[1A], Q LE AA[1B], SWITCH[4B])

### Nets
GND: C1.1 C2.2 C3.2 C4.2 C5.1 C6.1 C7.1
Q_LE_LPF_INPUT_N: C5.2 L3.1 ; port Q_LE_LPF_INPUT_N
Q_LE_LPF_INPUT_P: C2.1 L1.1 ; port Q_LE_LPF_INPUT_P
Q_LE_LPF_OUTPUT_N: R4.2 ; port Q_LE_LPF_OUTPUT_N
Q_LE_LPF_OUTPUT_P: R3.2 ; port Q_LE_LPF_OUTPUT_P
VCC: C1.2 R1.1 R2.2 ; port VCC
NetC3_1: C3.1 L1.2 L2.1
NetC4_1: C4.1 L2.2 R2.1 R3.1
NetC6_2: C6.2 L3.2 L4.1
NetC7_2: C7.2 L4.2 R1.2 R4.1

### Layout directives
net class R50: NetC3_1, NetC4_1, NetC6_2, NetC7_2

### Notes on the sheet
- QORVO_RADIO_SDR_Q_LE_LPF
- 10 OF 20
- 1
- NATHAN WATERS

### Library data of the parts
C1 = 0402_CAP: as C86 on sheet 3.3v REG
C2 C5 = 0402_CAP: as C92 on sheet I LE LPF
C3 C4 C6 C7 = 0603_CAP: as C93 on sheet I LE LPF
L1 L3 = 0402_IND: as L24 on sheet I LE LPF
L2 L4 = 0402_IND: as L25 on sheet I LE LPF
R1 R2 = 0402_RES: as R32 on sheet I LE LPF
R3 R4 = 0402_RES: as R34 on sheet I LE LPF

## Sheet I HE LPF.SchDoc
size A; SheetNumber: 11; SheetTotal: 20
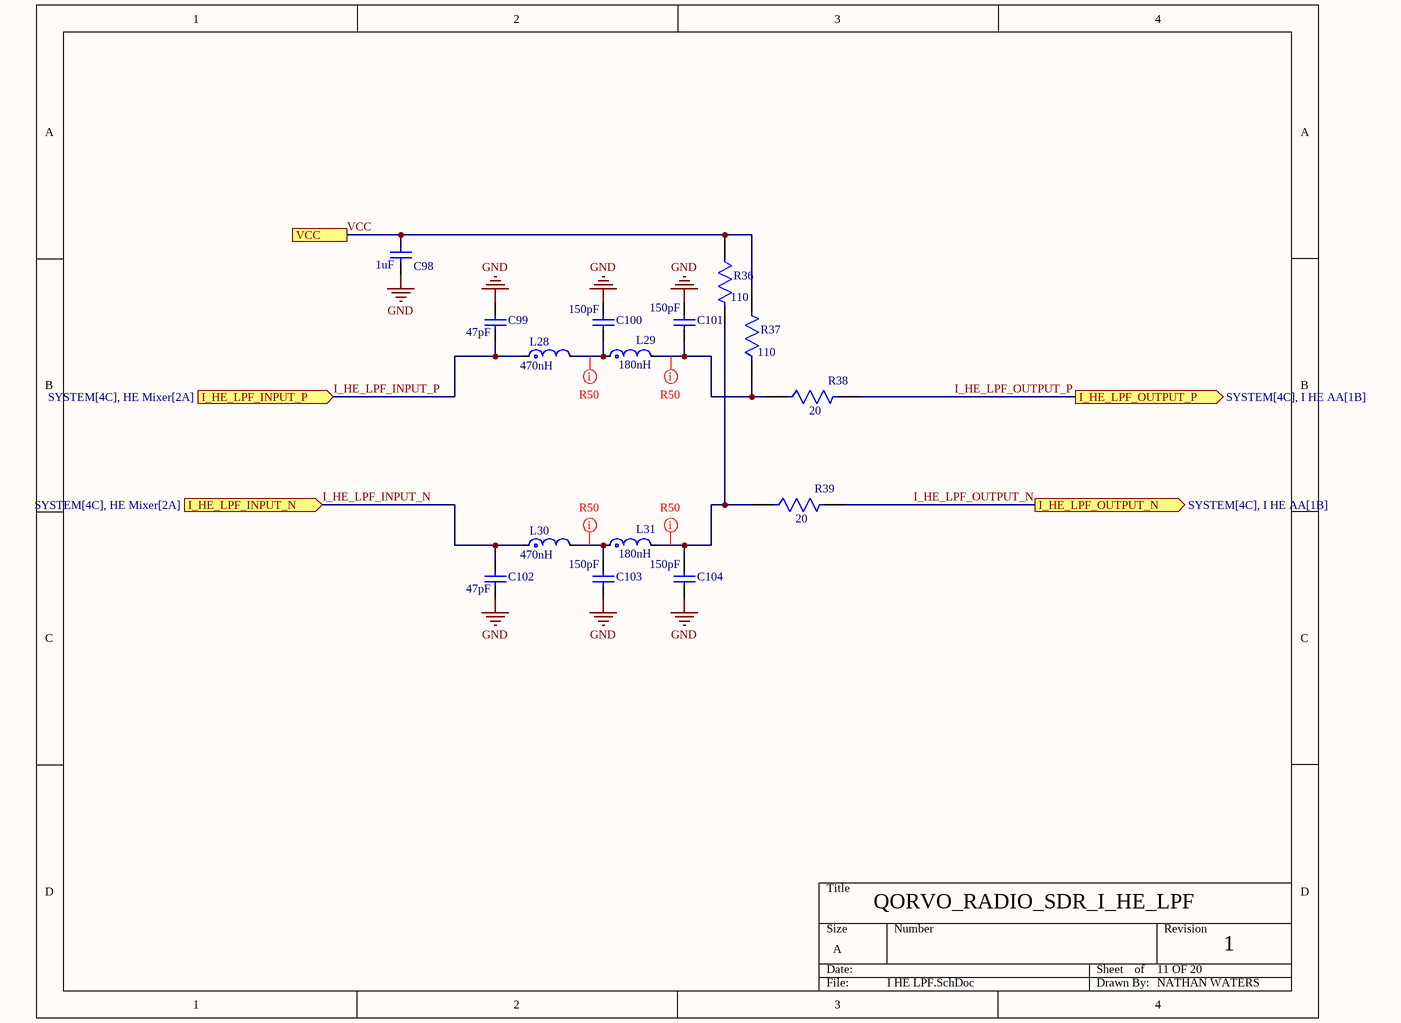
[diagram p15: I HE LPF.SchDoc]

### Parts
C98  CAPACITANCE: 1uF  [0402 CAP_IND_RES]  (hidden comment: GRM155R61H105KE05D)
C99  CAPACITANCE: 47pF  [0402 CAP_IND_RES]  (hidden comment: GJM1555C1H470FB01D)
C100  CAPACITANCE: 150pF  [0603_CAP]  (hidden comment: CC0603JRNPO9BN151)
C101  CAPACITANCE: 150pF  [0603_CAP]  (hidden comment: CC0603JRNPO9BN151)
C102  CAPACITANCE: 47pF  [0402 CAP_IND_RES]  (hidden comment: GJM1555C1H470FB01D)
C103  CAPACITANCE: 150pF  [0603_CAP]  (hidden comment: CC0603JRNPO9BN151)
C104  CAPACITANCE: 150pF  [0603_CAP]  (hidden comment: CC0603JRNPO9BN151)
L28  INDUCTANCE: 470nH  [0402 CAP_IND_RES]  (hidden comment: MWSD1005FR47JTM01)
L29  INDUCTANCE: 180nH  [0402 CAP_IND_RES]  (hidden comment: SDCL1005CR18JTDF)
L30  INDUCTANCE: 470nH  [0402 CAP_IND_RES]  (hidden comment: MWSD1005FR47JTM01)
L31  INDUCTANCE: 180nH  [0402 CAP_IND_RES]  (hidden comment: SDCL1005CR18JTDF)
R36  RESISTANCE: 110  [0402 CAP_IND_RES]  (hidden comment: CRCW0402110RFKED)
R37  RESISTANCE: 110  [0402 CAP_IND_RES]  (hidden comment: CRCW0402110RFKED)
R38  RESISTANCE: 20  [0402 CAP_IND_RES]  (hidden comment: CRCW040220R0FKED)
R39  RESISTANCE: 20  [0402 CAP_IND_RES]  (hidden comment: CRCW040220R0FKED)

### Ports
I_HE_LPF_INPUT_N (in, see SYSTEM[4C], HE Mixer[2A]), I_HE_LPF_INPUT_P (in, see SYSTEM[4C], HE Mixer[2A]), I_HE_LPF_OUTPUT_N (out, see SYSTEM[4C], I HE AA[1B]), I_HE_LPF_OUTPUT_P (out, see SYSTEM[4C], I HE AA[1B]), VCC (see SYSTEM[4C], 0.9V REG_1[3B], 0.9V REG_2[3B], 0.9V REG_3[3B], 0.9V REG_4[3B], 3.3v REG[3B], HE LNA[2A], HE Mixer[3C], I HE AA[1B], I LE AA[1B], I LE LPF[1A], LE LNA[2A], LE Mixer[3C], Q HE AA[1B], Q HE LPF[1A], Q LE AA[1B], Q LE LPF[1B], SWITCH[4B])

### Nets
GND: C98.1 C99.2 C100.2 C101.2 C102.1 C103.1 C104.1
I_HE_LPF_INPUT_N: C102.2 L30.1 ; port I_HE_LPF_INPUT_N
I_HE_LPF_INPUT_P: C99.1 L28.1 ; port I_HE_LPF_INPUT_P
I_HE_LPF_OUTPUT_N: R39.2 ; port I_HE_LPF_OUTPUT_N
I_HE_LPF_OUTPUT_P: R38.2 ; port I_HE_LPF_OUTPUT_P
VCC: C98.2 R36.1 R37.2 ; port VCC
NetC100_1: C100.1 L28.2 L29.1
NetC101_1: C101.1 L29.2 R37.1 R38.1
NetC103_2: C103.2 L30.2 L31.1
NetC104_2: C104.2 L31.2 R36.2 R39.1

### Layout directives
net class R50: NetC100_1, NetC101_1, NetC103_2, NetC104_2

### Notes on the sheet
- QORVO_RADIO_SDR_I_HE_LPF
- 11 OF 20
- 1
- NATHAN WATERS

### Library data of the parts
C98 = 0402_CAP: as C86 on sheet 3.3v REG
C99 C102 = 0402_CAP: as C92 on sheet I LE LPF
C100 C101 C103 C104 = 0603_CAP: as C93 on sheet I LE LPF
L28 L30 = 0402_IND: as L24 on sheet I LE LPF
L29 L31 = 0402_IND: as L25 on sheet I LE LPF
R36 R37 = 0402_RES: as R32 on sheet I LE LPF
R38 R39 = 0402_RES: as R34 on sheet I LE LPF

## Sheet Q HE LPF.SchDoc
size A; SheetNumber: 12; SheetTotal: 20
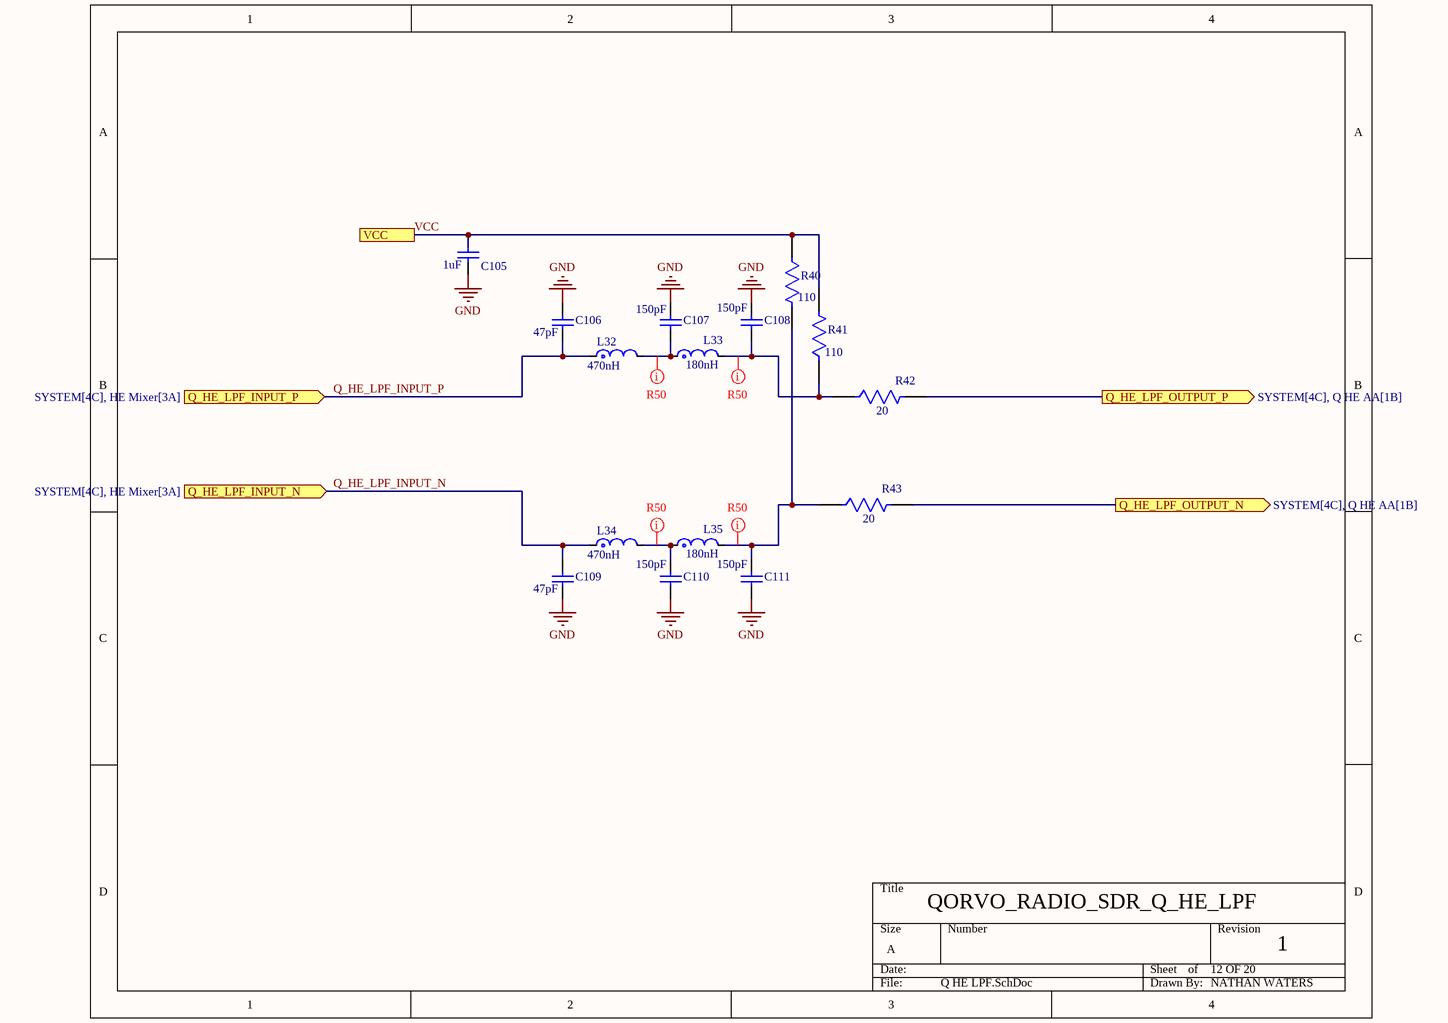
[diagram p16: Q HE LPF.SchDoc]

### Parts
C105  CAPACITANCE: 1uF  [0402 CAP_IND_RES]  (hidden comment: GRM155R61H105KE05D)
C106  CAPACITANCE: 47pF  [0402 CAP_IND_RES]  (hidden comment: GJM1555C1H470FB01D)
C107  CAPACITANCE: 150pF  [0603_CAP]  (hidden comment: CC0603JRNPO9BN151)
C108  CAPACITANCE: 150pF  [0603_CAP]  (hidden comment: CC0603JRNPO9BN151)
C109  CAPACITANCE: 47pF  [0402 CAP_IND_RES]  (hidden comment: GJM1555C1H470FB01D)
C110  CAPACITANCE: 150pF  [0603_CAP]  (hidden comment: CC0603JRNPO9BN151)
C111  CAPACITANCE: 150pF  [0603_CAP]  (hidden comment: CC0603JRNPO9BN151)
L32  INDUCTANCE: 470nH  [0402 CAP_IND_RES]  (hidden comment: MWSD1005FR47JTM01)
L33  INDUCTANCE: 180nH  [0402 CAP_IND_RES]  (hidden comment: SDCL1005CR18JTDF)
L34  INDUCTANCE: 470nH  [0402 CAP_IND_RES]  (hidden comment: MWSD1005FR47JTM01)
L35  INDUCTANCE: 180nH  [0402 CAP_IND_RES]  (hidden comment: SDCL1005CR18JTDF)
R40  RESISTANCE: 110  [0402 CAP_IND_RES]  (hidden comment: CRCW0402110RFKED)
R41  RESISTANCE: 110  [0402 CAP_IND_RES]  (hidden comment: CRCW0402110RFKED)
R42  RESISTANCE: 20  [0402 CAP_IND_RES]  (hidden comment: CRCW040220R0FKED)
R43  RESISTANCE: 20  [0402 CAP_IND_RES]  (hidden comment: CRCW040220R0FKED)

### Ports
Q_HE_LPF_INPUT_N (in, see SYSTEM[4C], HE Mixer[3A]), Q_HE_LPF_INPUT_P (in, see SYSTEM[4C], HE Mixer[3A]), Q_HE_LPF_OUTPUT_N (out, see SYSTEM[4C], Q HE AA[1B]), Q_HE_LPF_OUTPUT_P (out, see SYSTEM[4C], Q HE AA[1B]), VCC (see SYSTEM[4C], 0.9V REG_1[3B], 0.9V REG_2[3B], 0.9V REG_3[3B], 0.9V REG_4[3B], 3.3v REG[3B], HE LNA[2A], HE Mixer[3C], I HE AA[1B], I HE LPF[1A], I LE AA[1B], I LE LPF[1A], LE LNA[2A], LE Mixer[3C], Q HE AA[1B], Q LE AA[1B], Q LE LPF[1B], SWITCH[4B])

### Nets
GND: C105.1 C106.2 C107.2 C108.2 C109.1 C110.1 C111.1
Q_HE_LPF_INPUT_N: C109.2 L34.1 ; port Q_HE_LPF_INPUT_N
Q_HE_LPF_INPUT_P: C106.1 L32.1 ; port Q_HE_LPF_INPUT_P
Q_HE_LPF_OUTPUT_N: R43.2 ; port Q_HE_LPF_OUTPUT_N
Q_HE_LPF_OUTPUT_P: R42.2 ; port Q_HE_LPF_OUTPUT_P
VCC: C105.2 R40.1 R41.2 ; port VCC
NetC107_1: C107.1 L32.2 L33.1
NetC108_1: C108.1 L33.2 R41.1 R42.1
NetC110_2: C110.2 L34.2 L35.1
NetC111_2: C111.2 L35.2 R40.2 R43.1

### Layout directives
net class R50: NetC107_1, NetC108_1, NetC110_2, NetC111_2

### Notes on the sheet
- QORVO_RADIO_SDR_Q_HE_LPF
- 12 OF 20
- 1
- NATHAN WATERS

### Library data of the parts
C105 = 0402_CAP: as C86 on sheet 3.3v REG
C106 C109 = 0402_CAP: as C92 on sheet I LE LPF
C107 C108 C110 C111 = 0603_CAP: as C93 on sheet I LE LPF
L32 L34 = 0402_IND: as L24 on sheet I LE LPF
L33 L35 = 0402_IND: as L25 on sheet I LE LPF
R40 R41 = 0402_RES: as R32 on sheet I LE LPF
R42 R43 = 0402_RES: as R34 on sheet I LE LPF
